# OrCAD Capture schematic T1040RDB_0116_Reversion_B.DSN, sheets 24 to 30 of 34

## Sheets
24 24 POTS3&4: size B
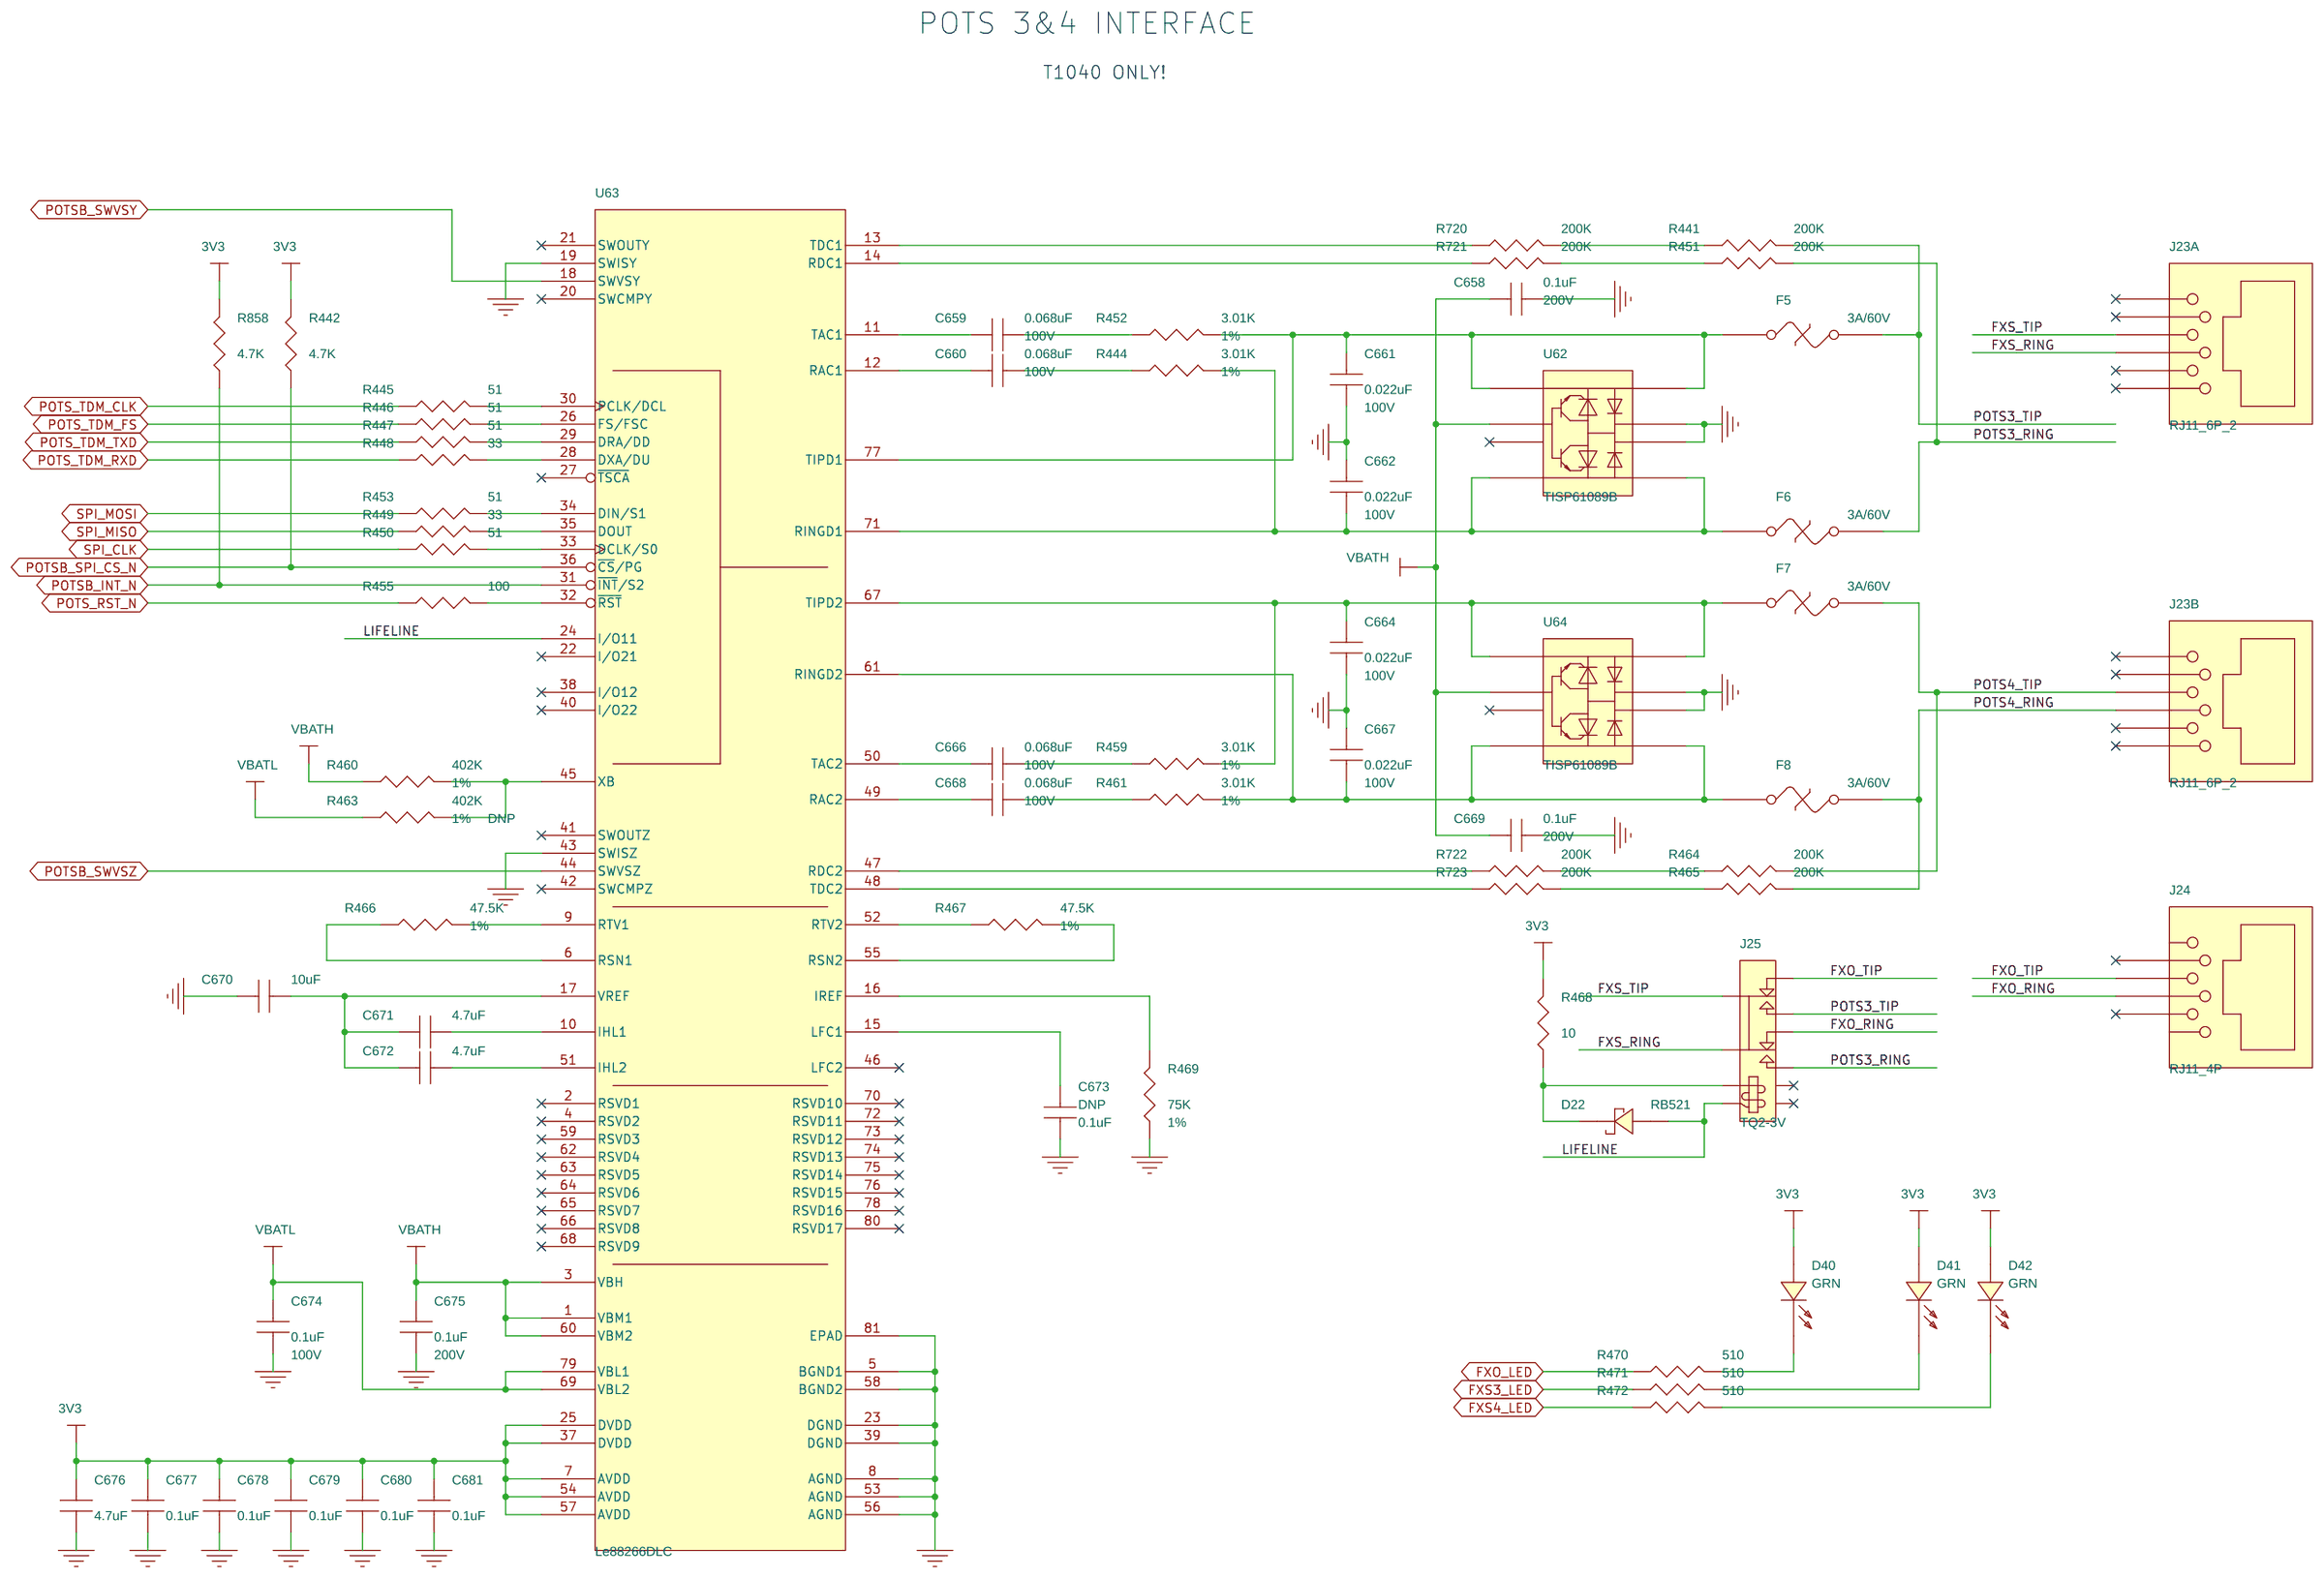
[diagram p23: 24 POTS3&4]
25 25 POTS Pwr: size B
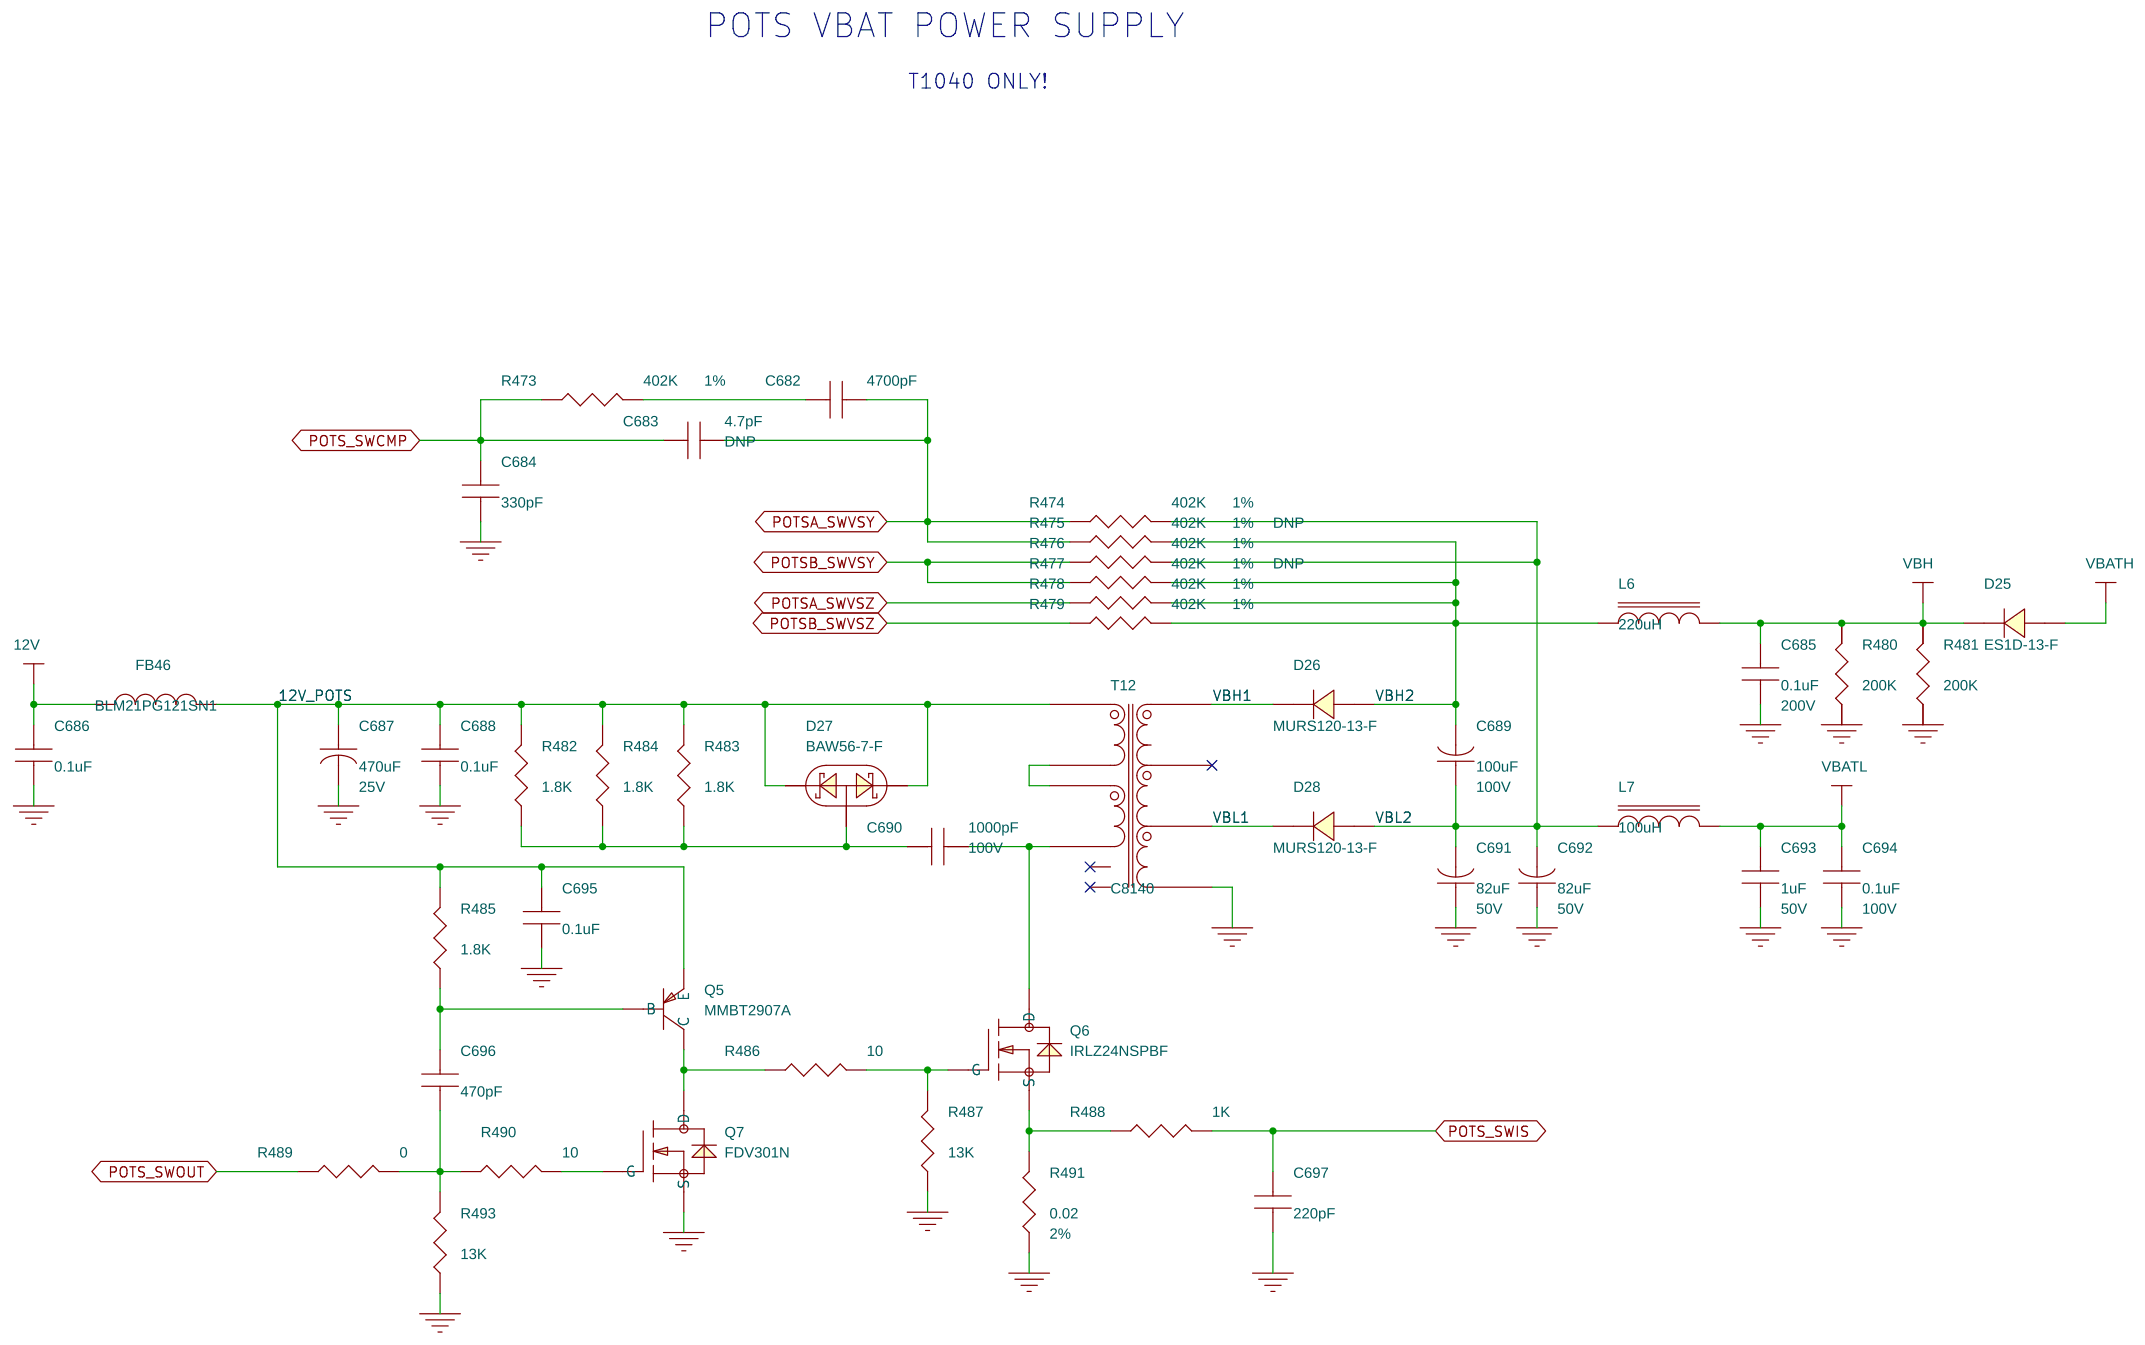
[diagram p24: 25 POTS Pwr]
26 26 CPLD: size B
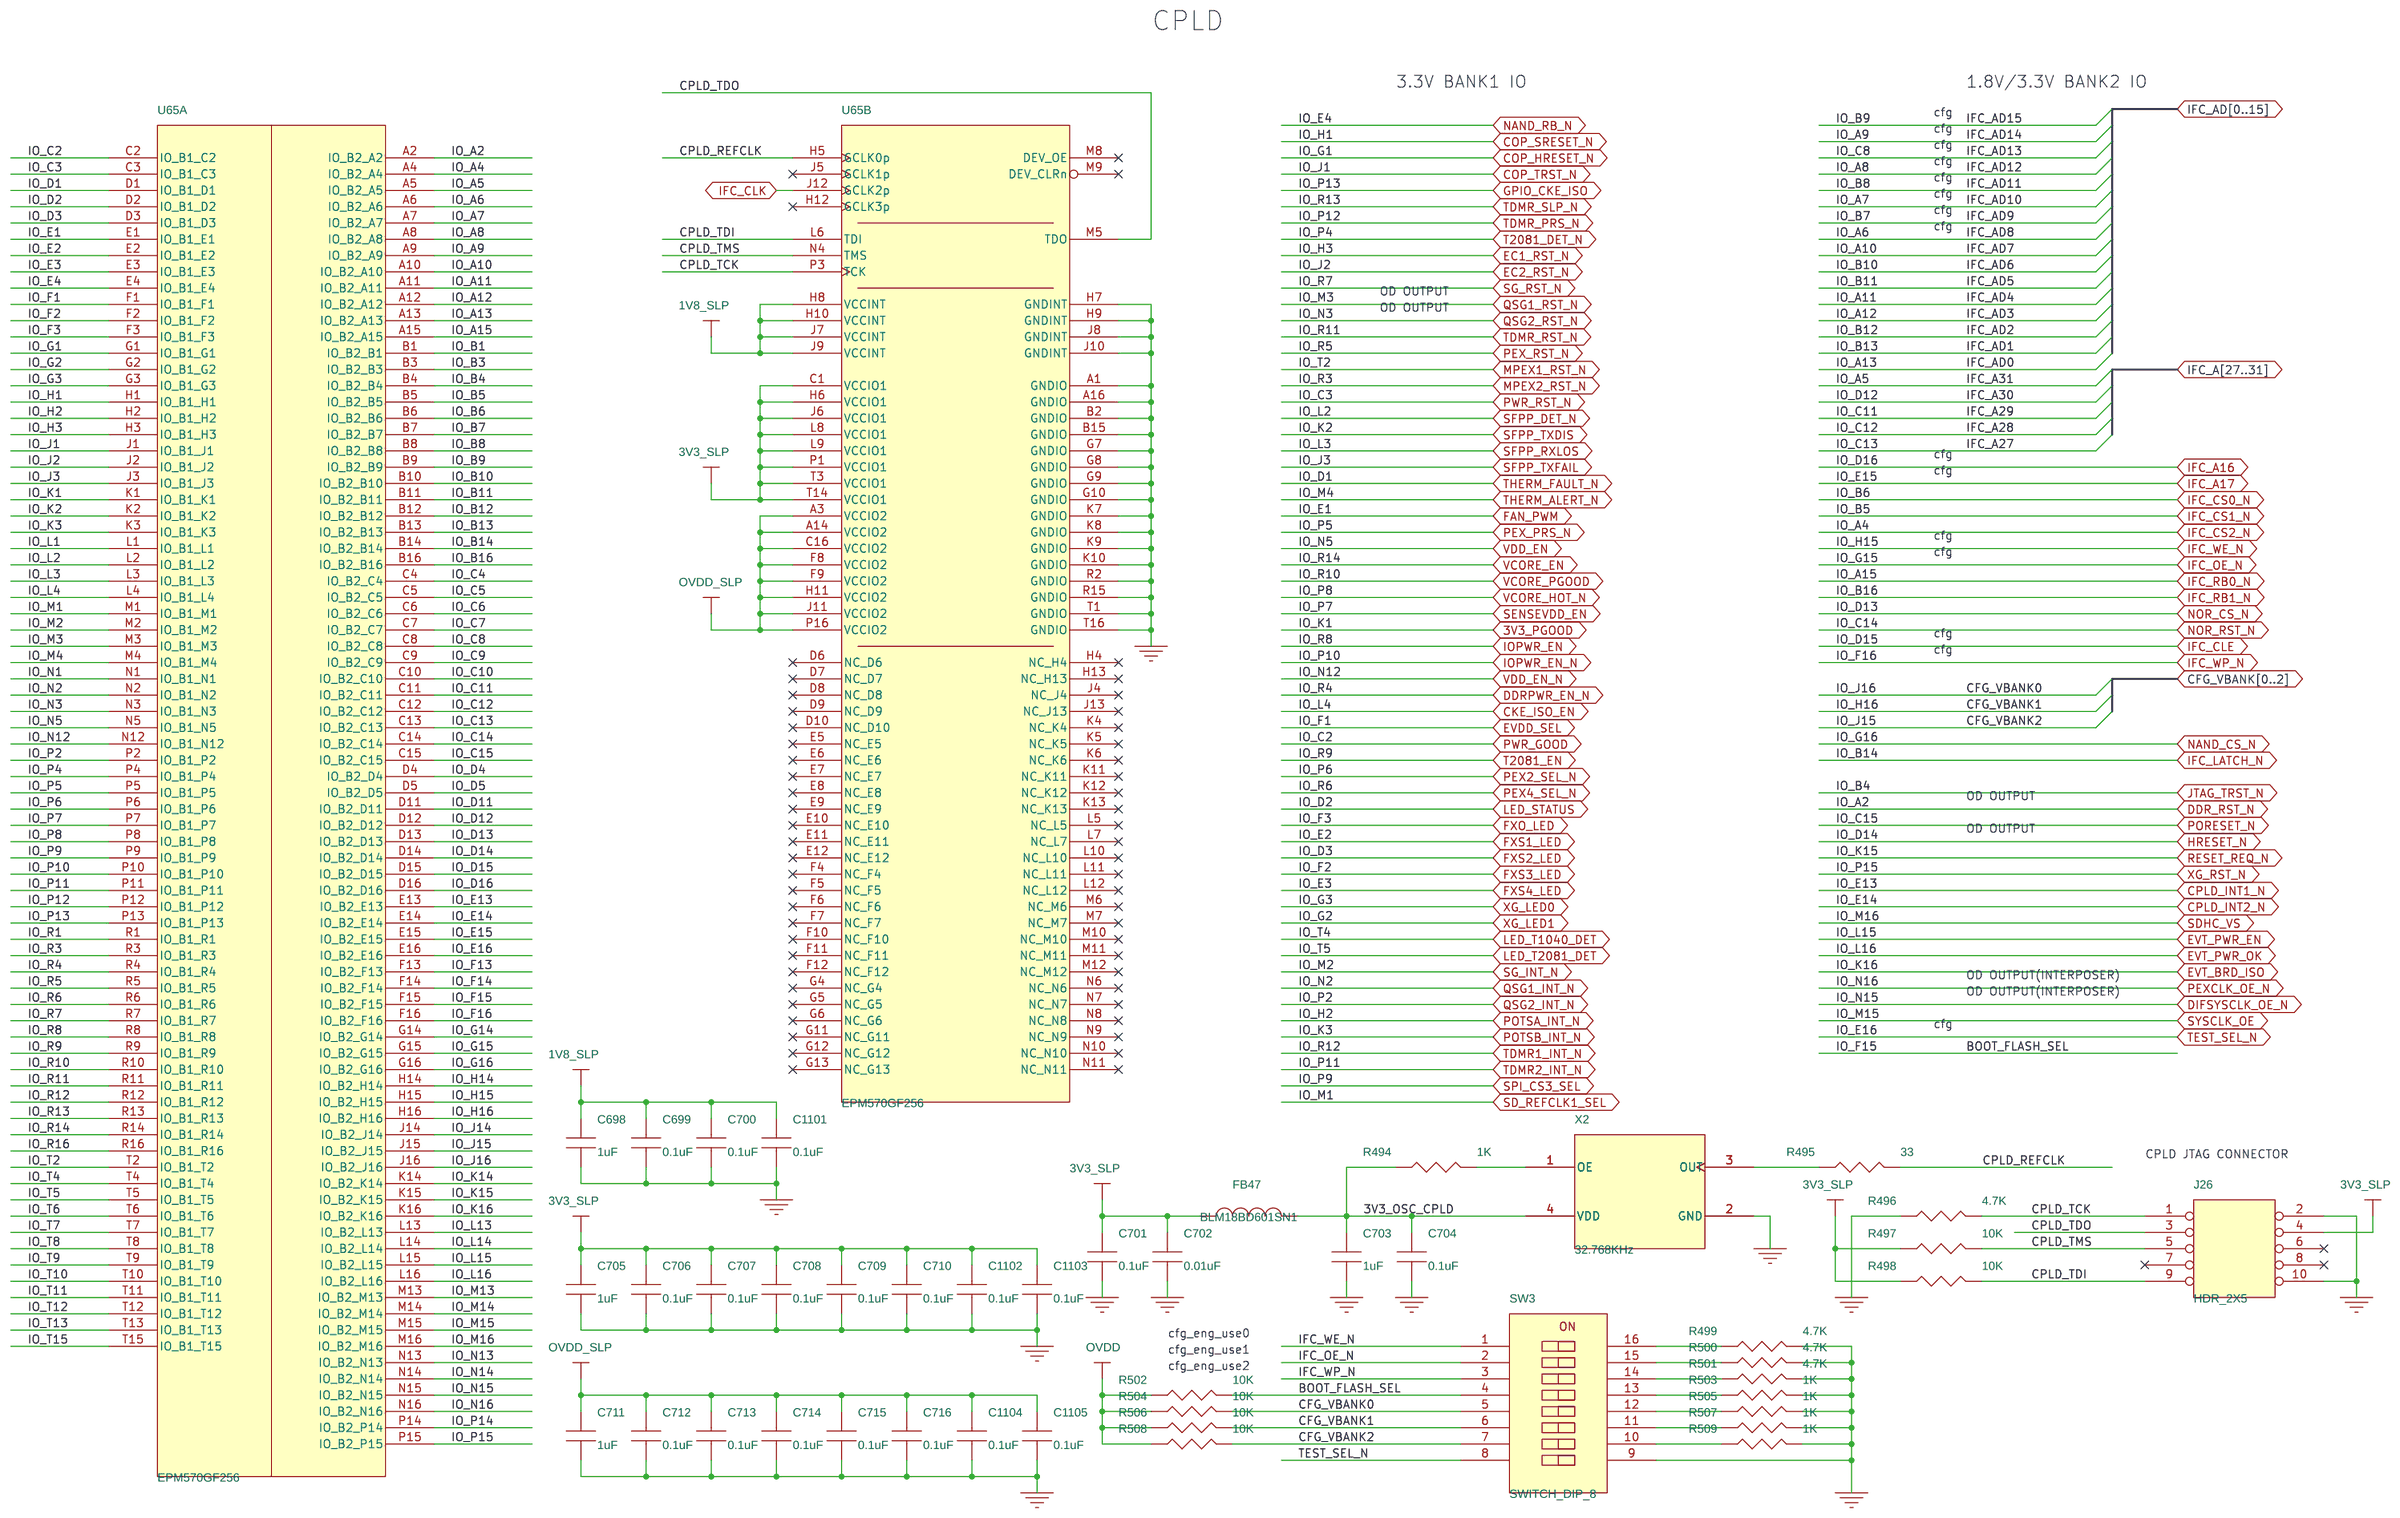
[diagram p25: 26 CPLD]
27 27 Clock 1: size B
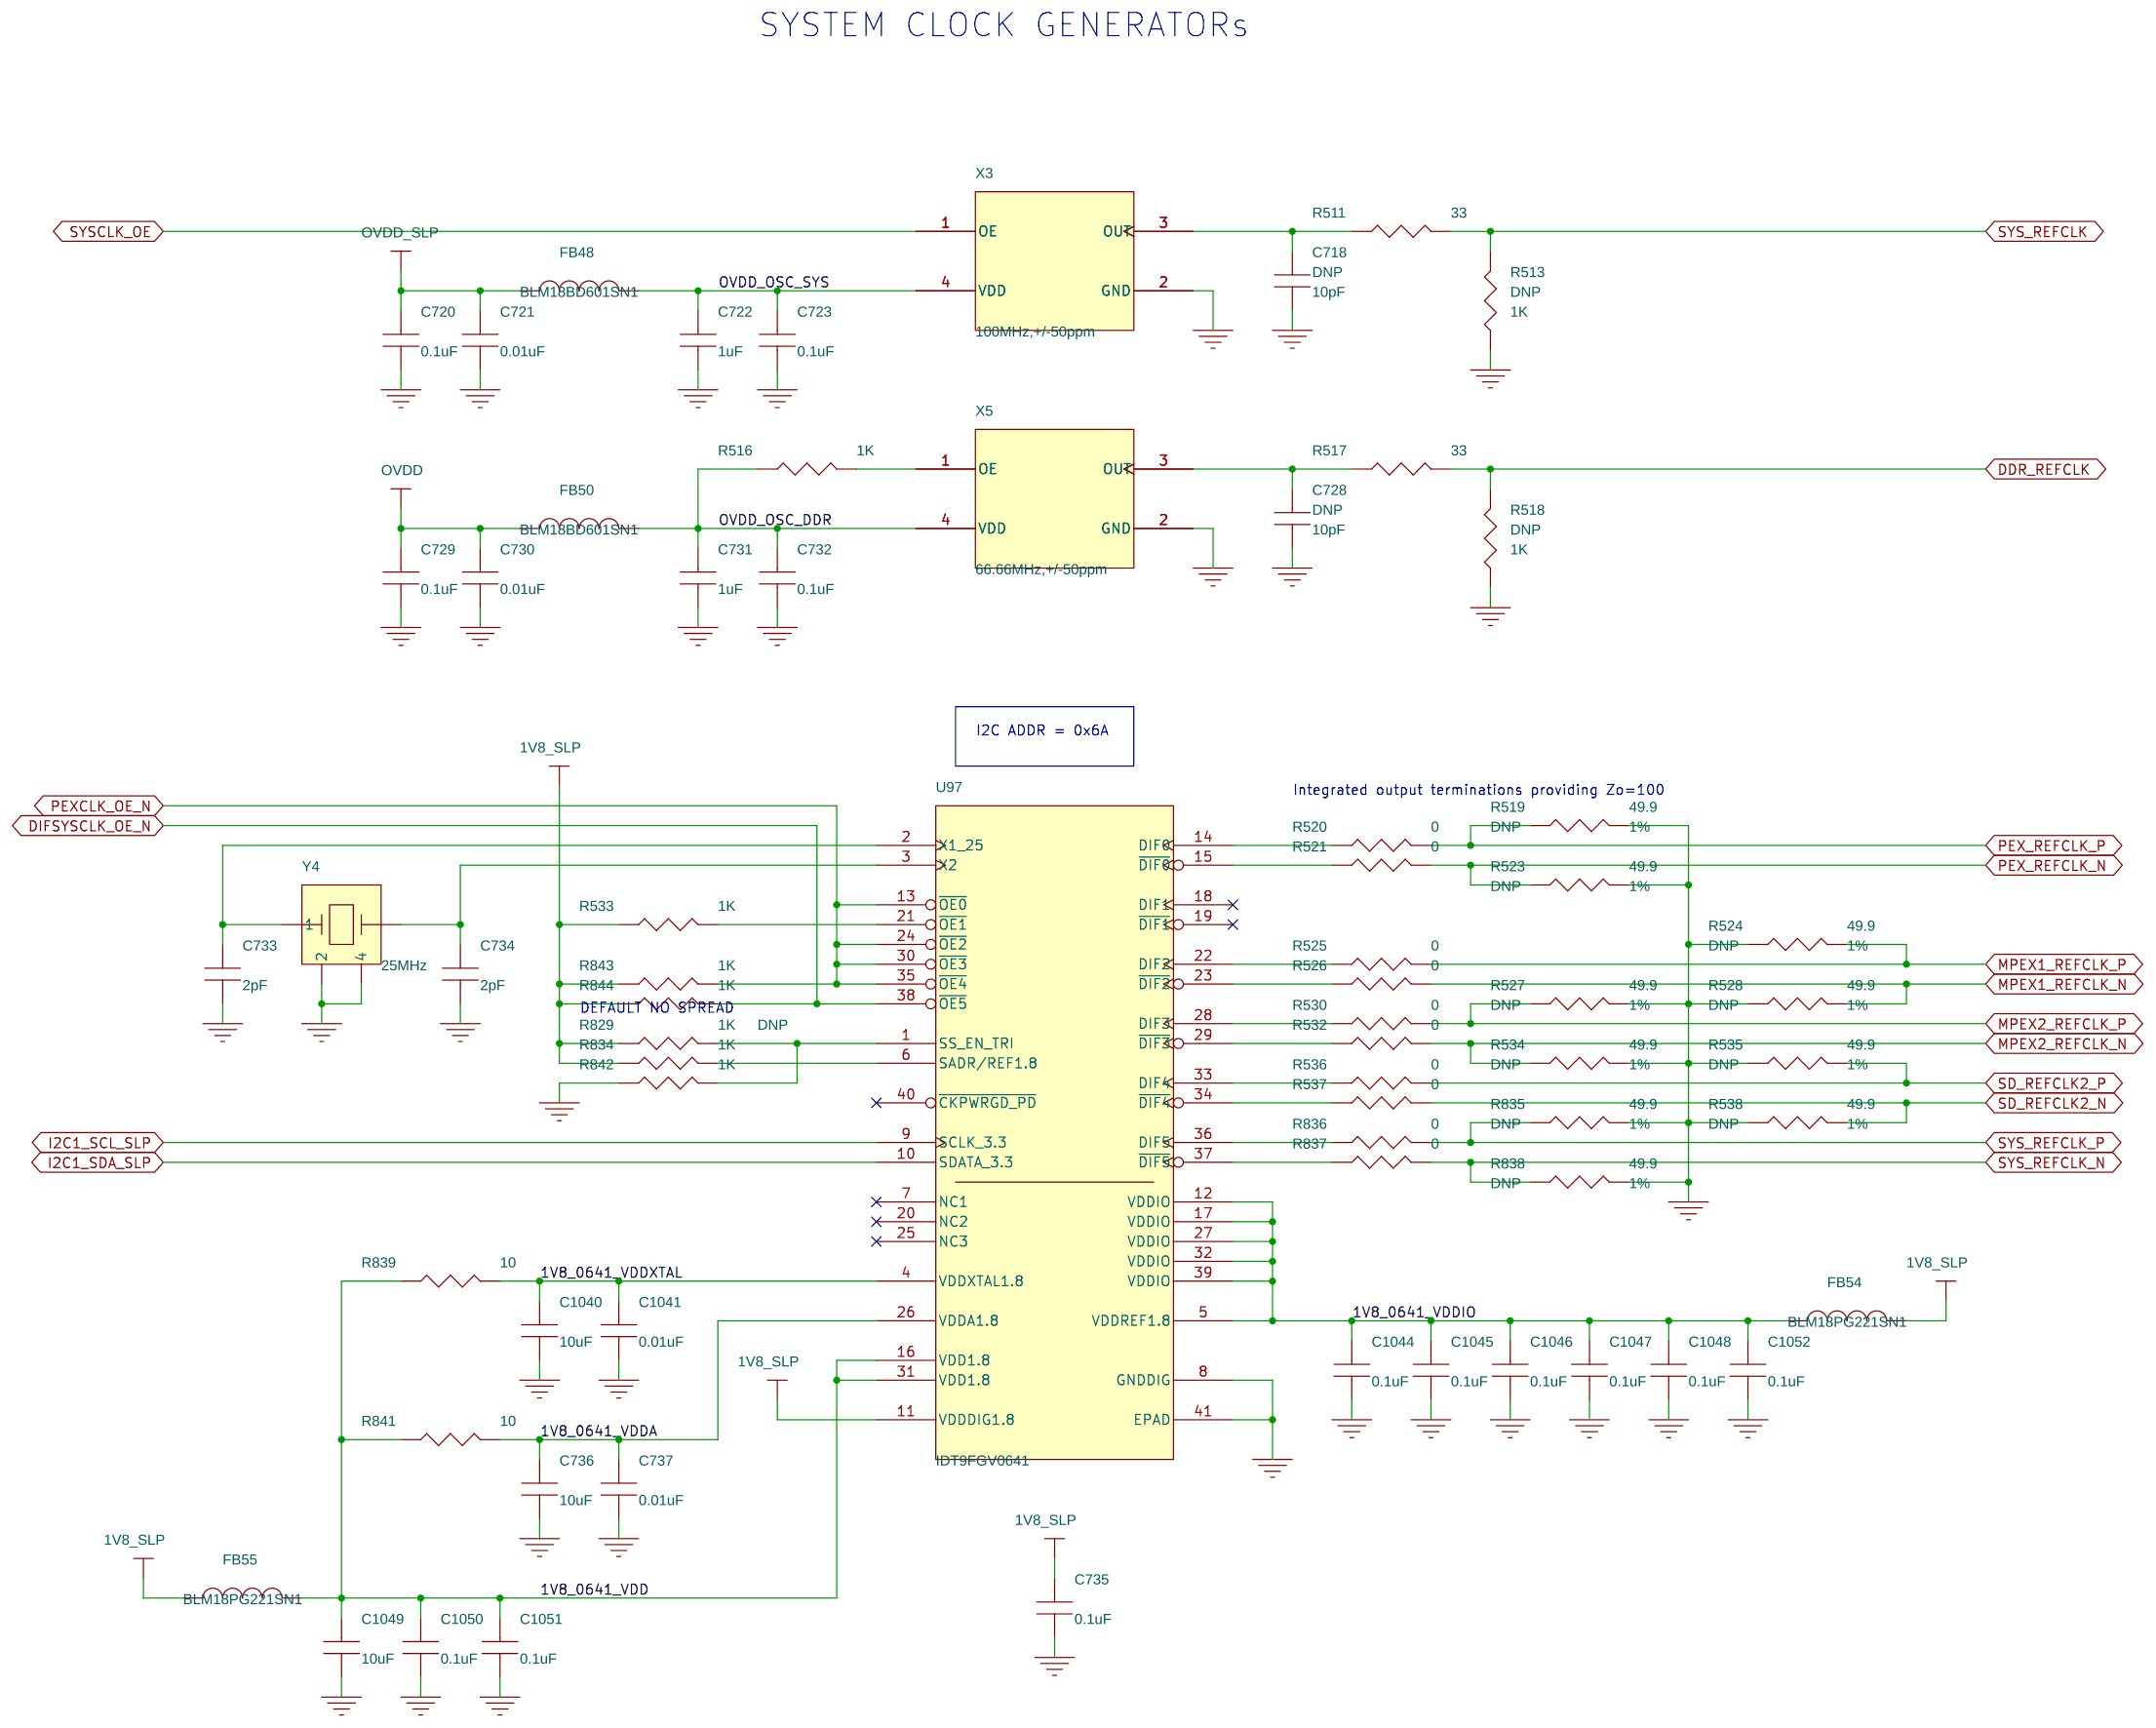
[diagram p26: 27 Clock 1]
28 28 Clock 2: size B
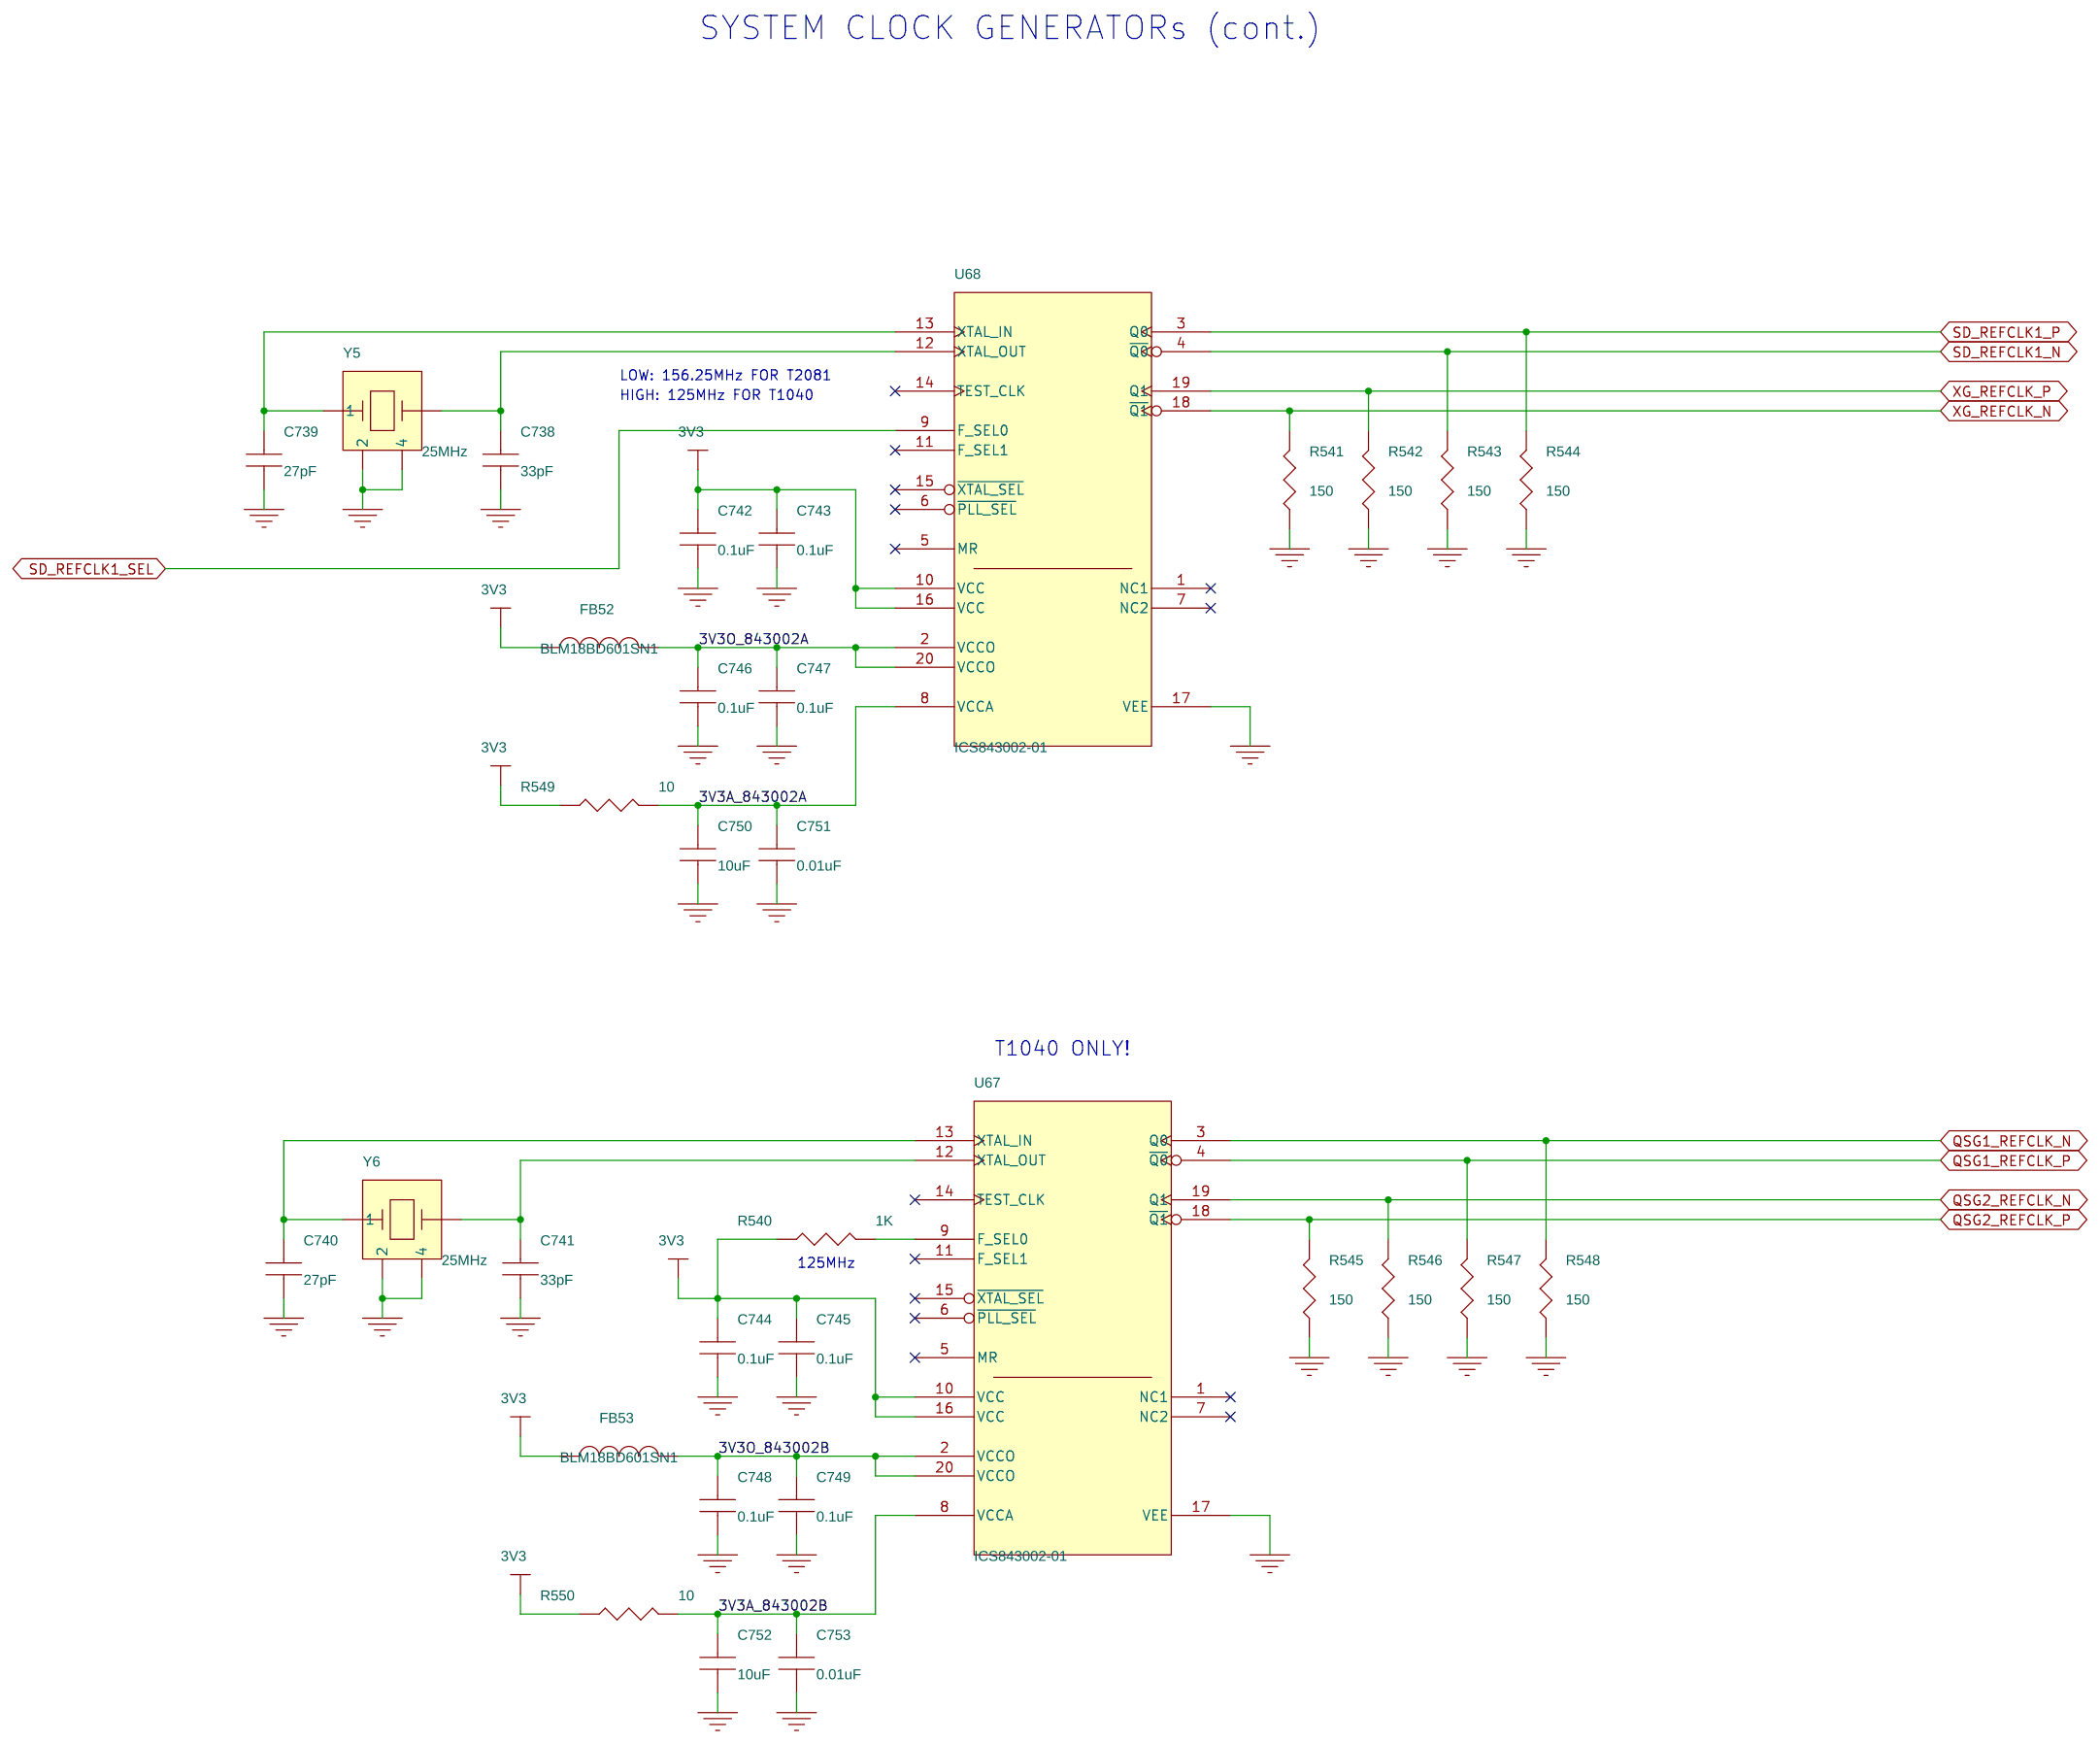
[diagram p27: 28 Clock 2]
29 29 Core Pwr: size B
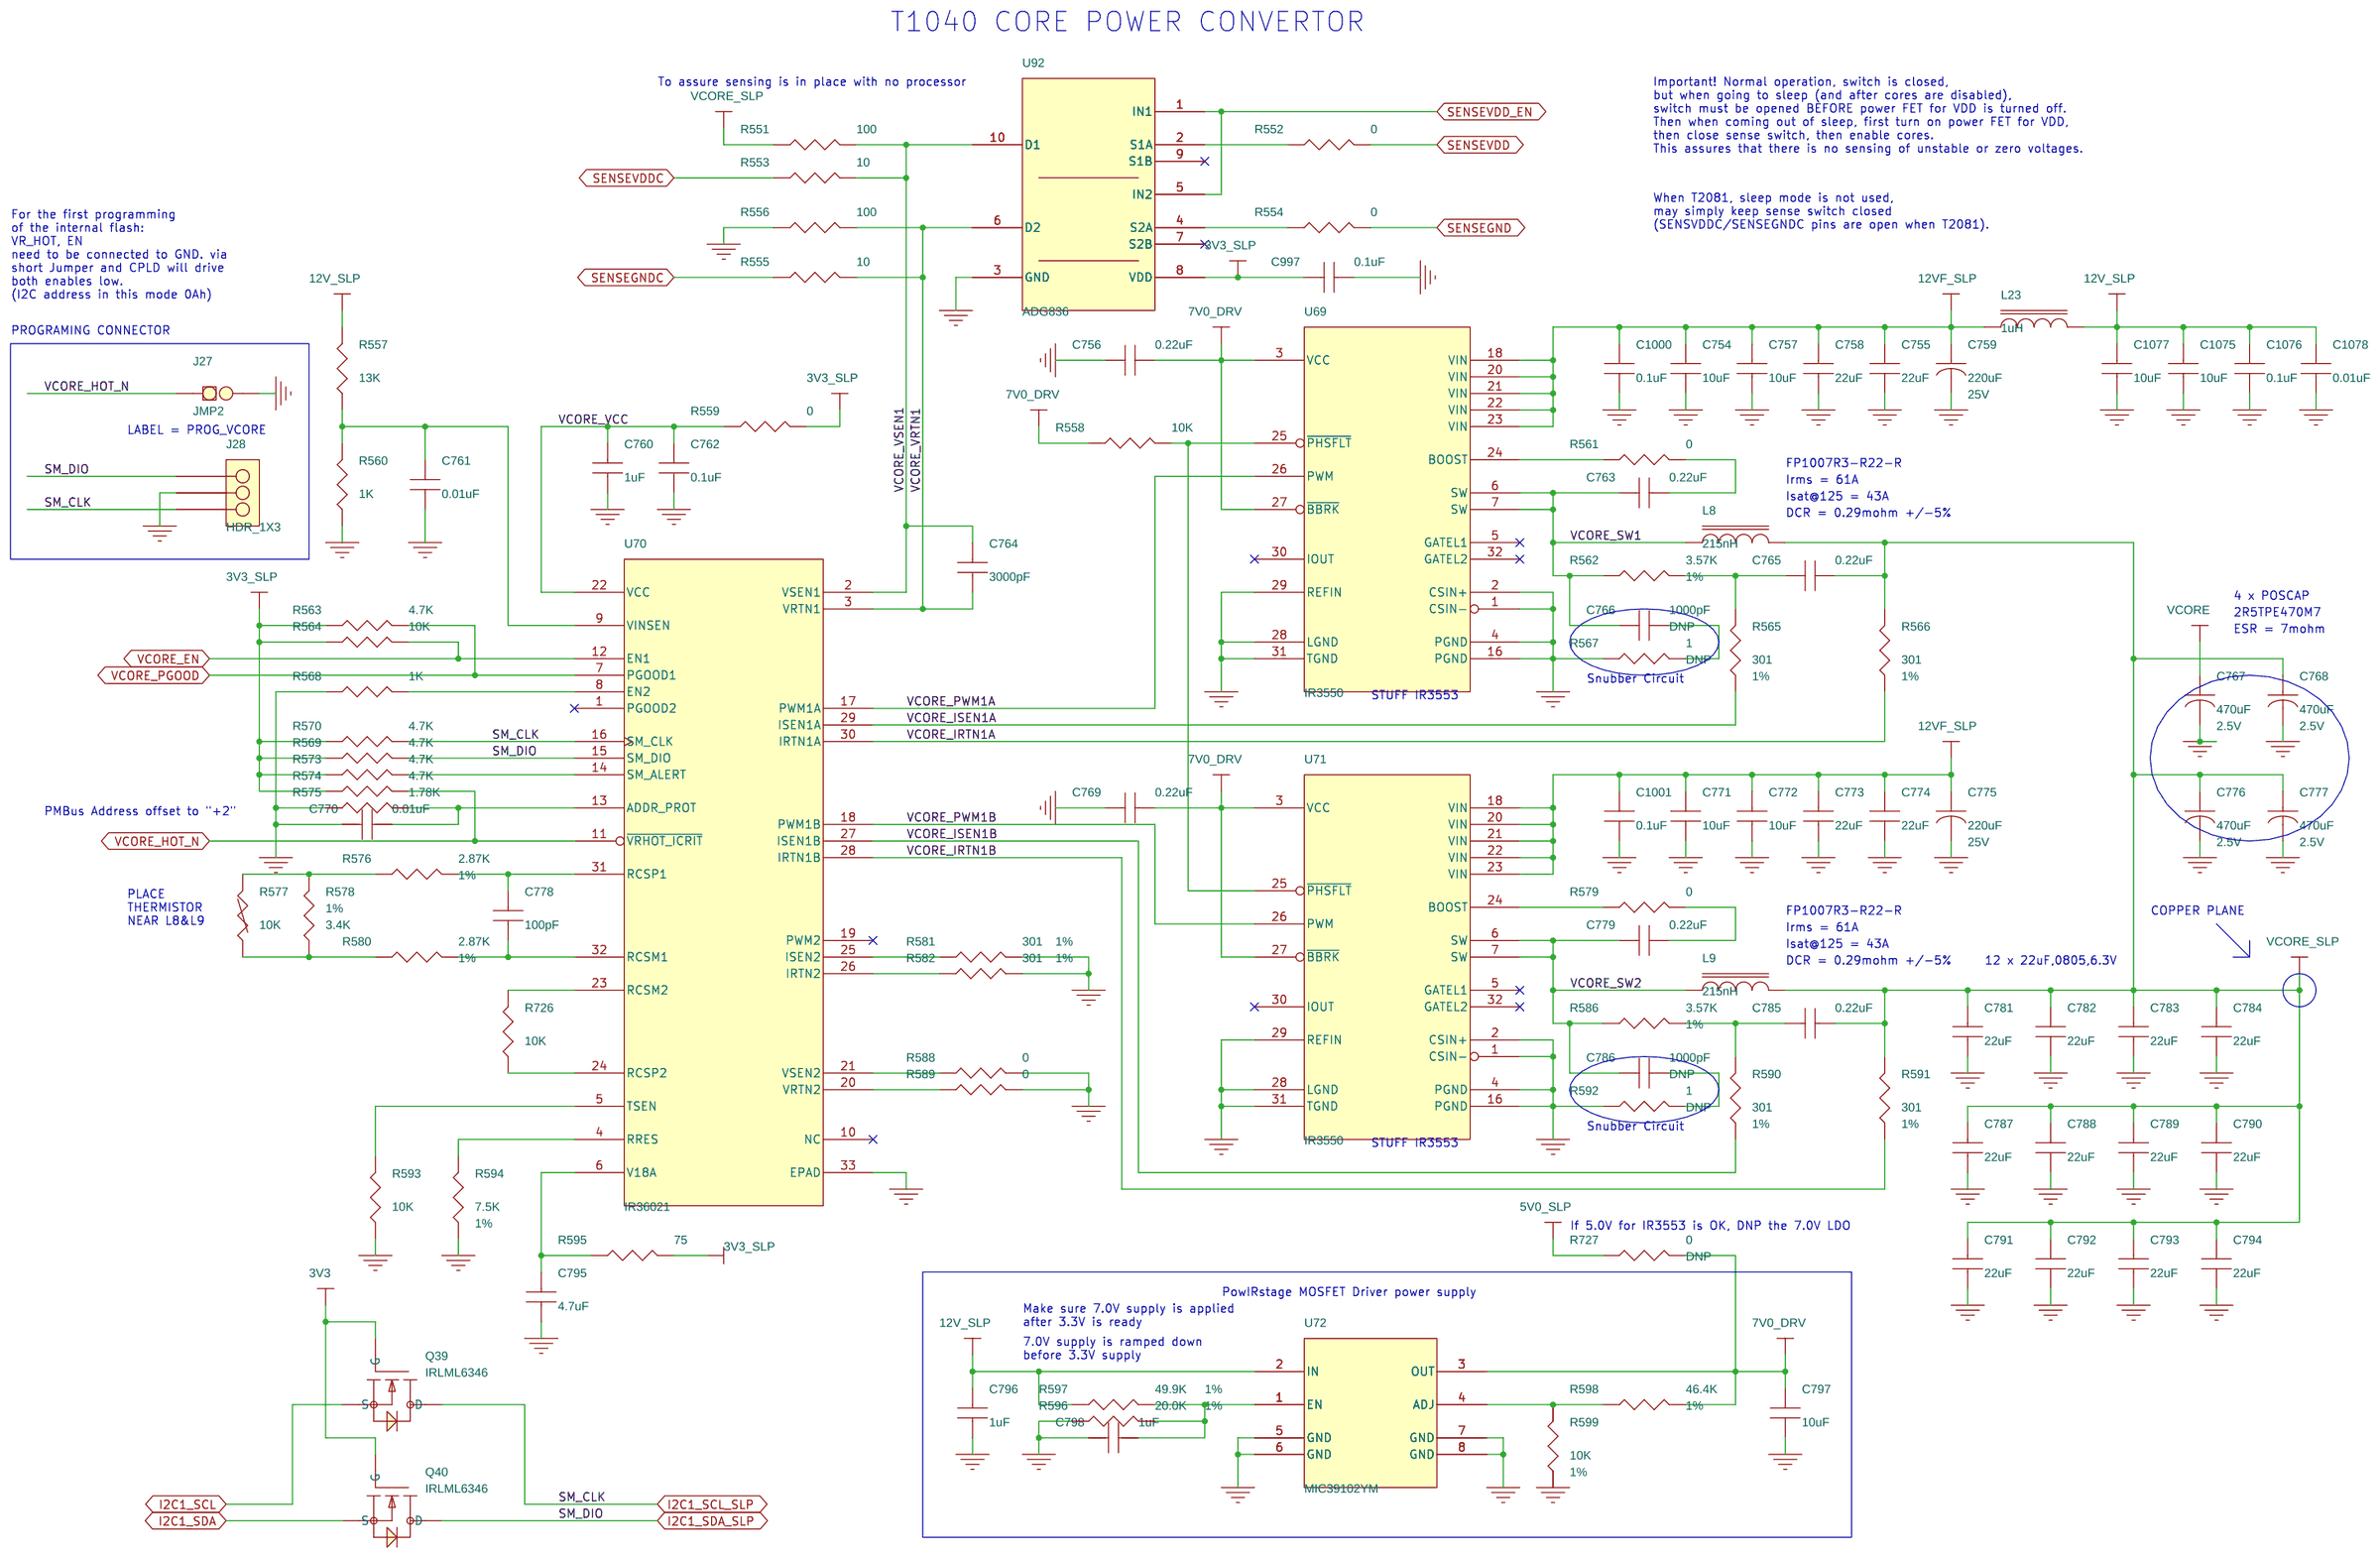
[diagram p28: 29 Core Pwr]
30 30 Other Pwr: size B
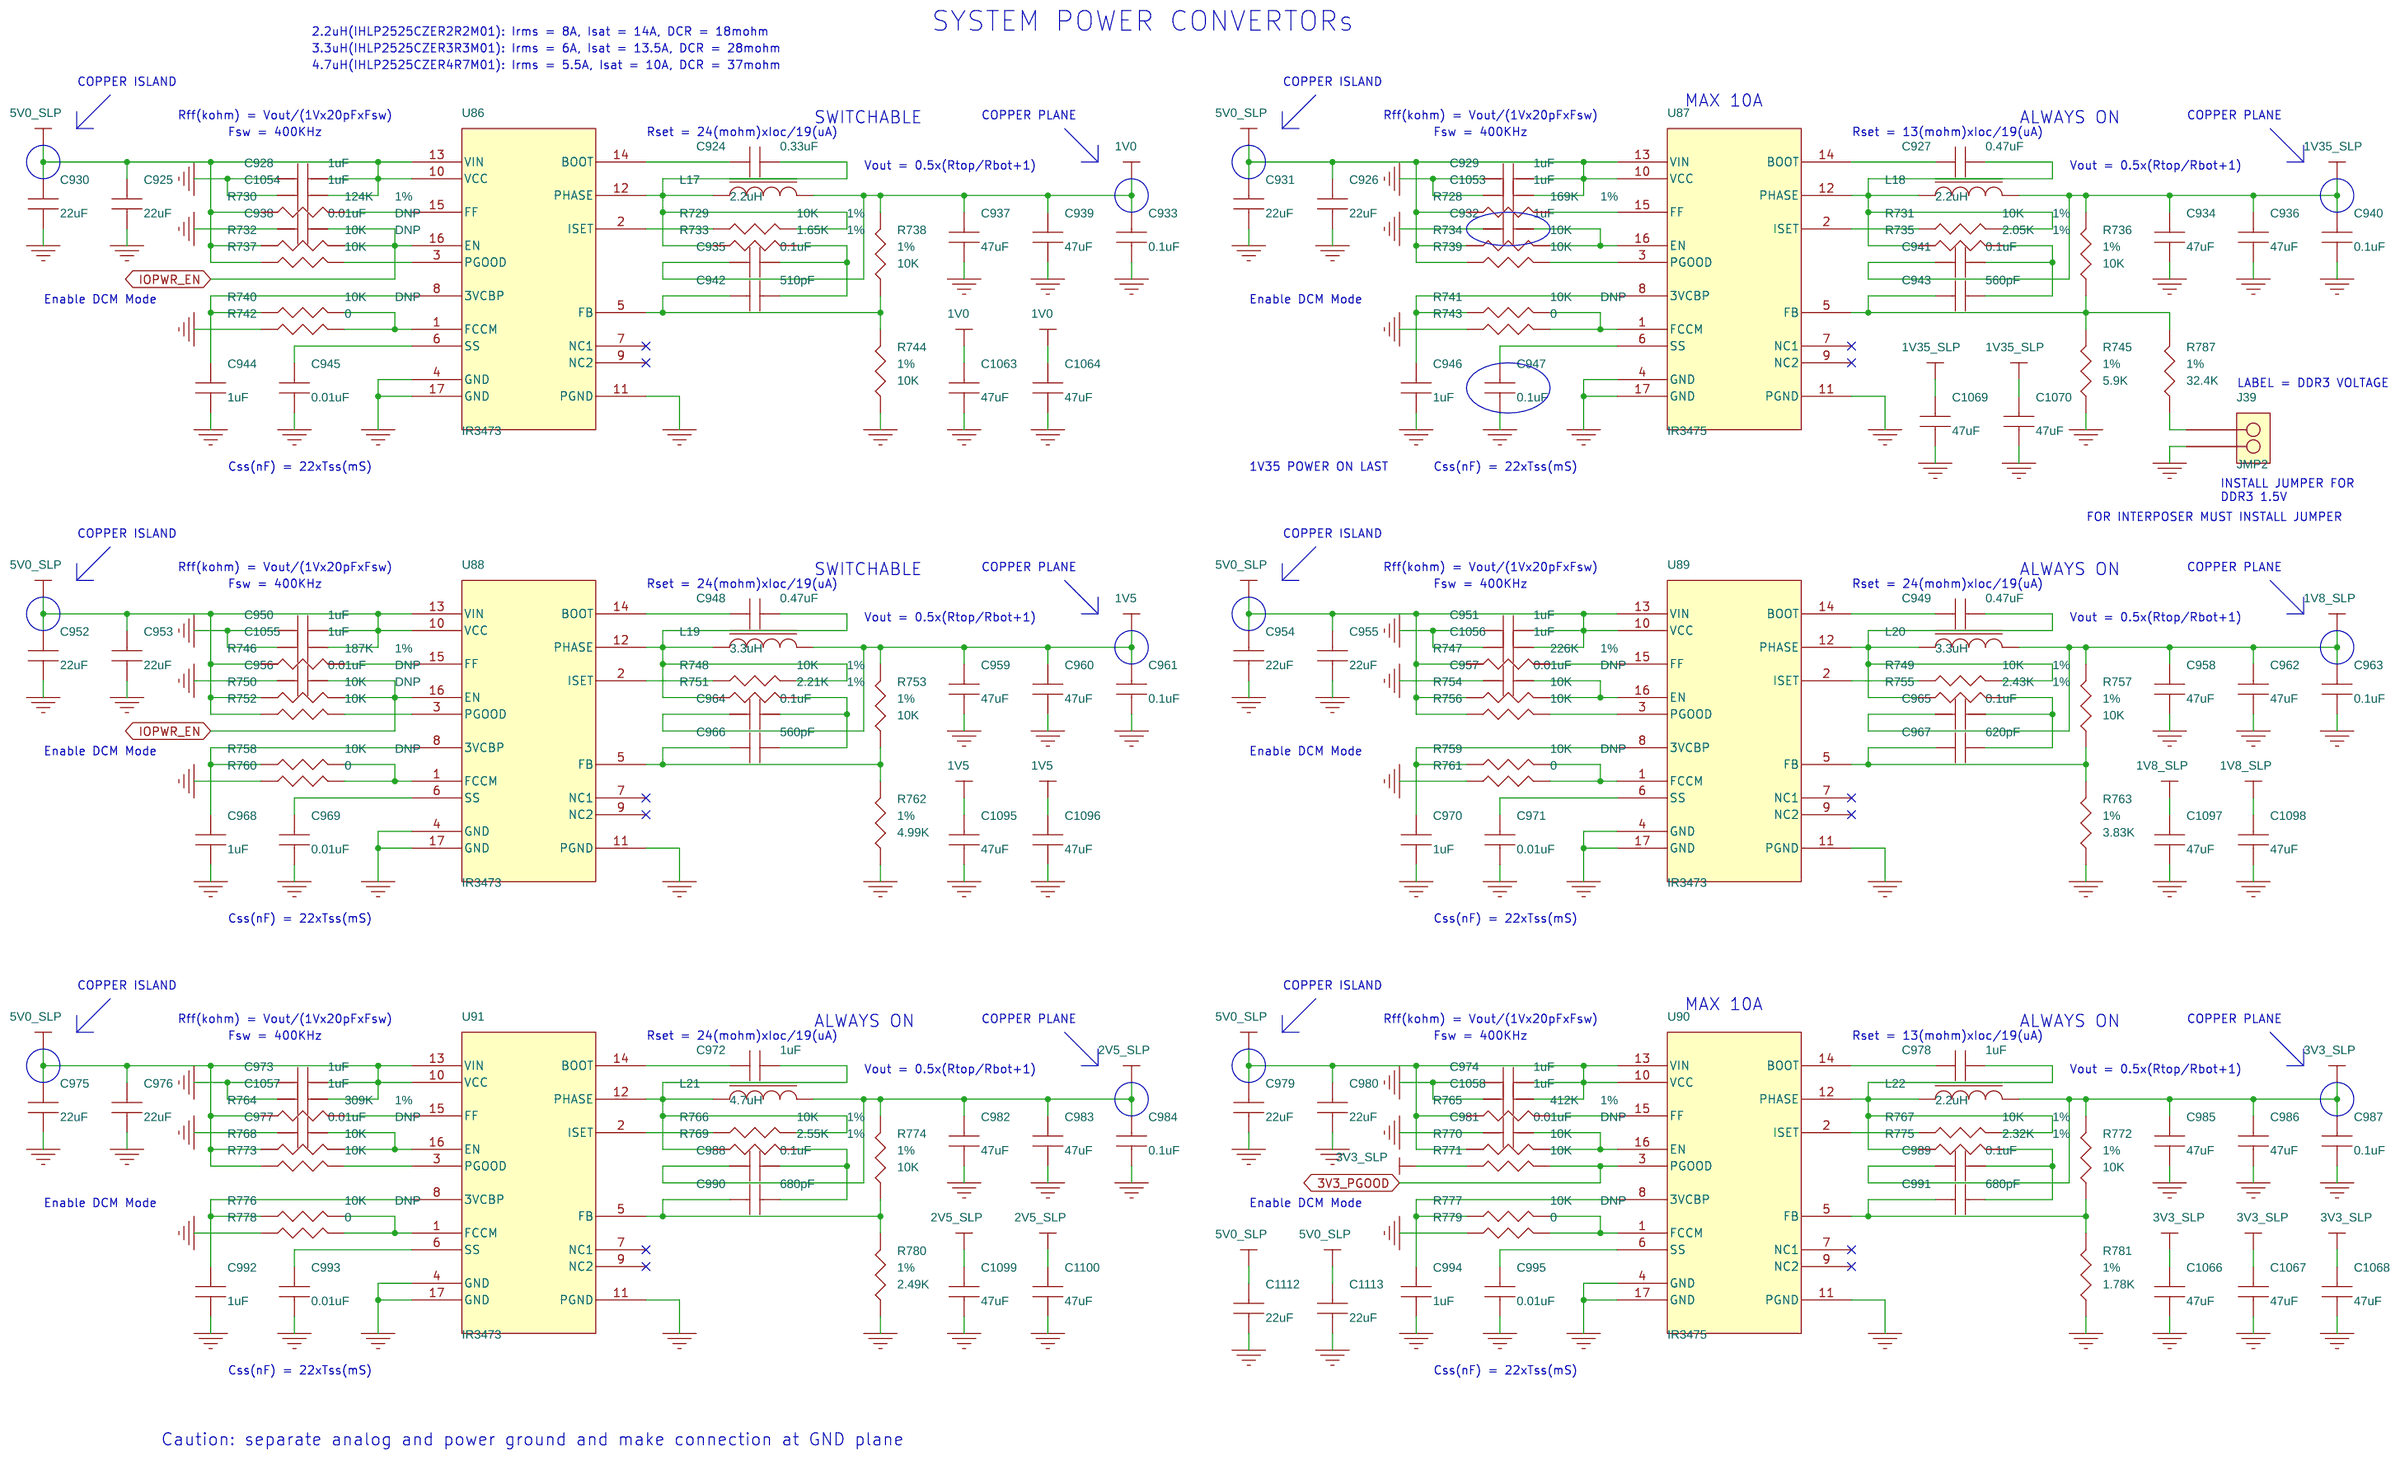
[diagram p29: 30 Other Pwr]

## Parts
sheet 24 POTS3&4
C658  0.1uF  [1206]
C659  0.068uF  [0805]
C660  0.068uF  [0805]
C661  0.022uF  [0805]
C662  0.022uF  [0805]
C664  0.022uF  [0805]
C666  0.068uF  [0805]
C667  0.022uF  [0805]
C668  0.068uF  [0805]
C669  0.1uF  [1206]
C670  10uF  [0603]
C671  4.7uF  [0603]
C672  4.7uF  [0603]
C673  0.1uF  [0402]
C674  0.1uF  [1206]
C675  0.1uF  [1206]
C676  4.7uF  [0603]
C677  0.1uF  [0402]
C678  0.1uF  [0402]
C679  0.1uF  [0402]
C680  0.1uF  [0402]
C681  0.1uF  [0402]
D22  RB521  [sod523]
D40  GRN  [led_pm_1s]
D41  GRN  [led_pm_1s]
D42  GRN  [led_pm_1s]
F5  3A/60V  [ptc_sm013]
F6  3A/60V  [ptc_sm013]
F7  3A/60V  [ptc_sm013]
F8  3A/60V  [ptc_sm013]
J23  RJ11_6P_2  [con_rj11_6p_2x1]  (sections A,B)
J24  RJ11_4P  [con_rj11_4p_1x1]
J25  TQ2-3V  [relay_tq2]
R441  200K  [1206]
R442  4.7K  [0402]
R444  3.01K  [0805]
R445  51  [0402]
R446  51  [0402]
R447  51  [0402]
R448  33  [0402]
R449  33  [0402]
R450  51  [0402]
R451  200K  [1206]
R452  3.01K  [0805]
R453  51  [0402]
R455  100  [0402]
R459  3.01K  [0805]
R460  402K  [0805]
R461  3.01K  [0805]
R463  402K  [0805]
R464  200K  [1206]
R465  200K  [1206]
R466  47.5K  [0402]
R467  47.5K  [0402]
R468  10  [0402]
R469  75K  [0402]
R470  510  [0402]
R471  510  [0402]
R472  510  [0402]
R720  200K  [1206]
R721  200K  [1206]
R722  200K  [1206]
R723  200K  [1206]
R858  4.7K  [0402]
U62  TISP61089B  [so_8]
U63  Le88266DLC  [qfp_p065_80_e780]
U64  TISP61089B  [so_8]
sheet 25 POTS Pwr
C682  4700pF  [0402]
C683  4.7pF  [0402]
C684  330pF  [0402]
C685  0.1uF  [1206]
C686  0.1uF  [0603]
C687  470uF  [cape_p5_b10]
C688  0.1uF  [0603]
C689  100uF  [cape_p5_b12d5]
C690  1000pF  [0603]
C691  82uF  [cape_p3d5_b8]
C692  82uF  [cape_p3d5_b8]
C693  1uF  [1206]
C694  0.1uF  [1206]
C695  0.1uF  [0603]
C696  470pF  [0402]
C697  220pF  [0402]
D25  ES1D-13-F  [sma]
D26  MURS120-13-F  [smb]
D27  BAW56-7-F  [sot23]
D28  MURS120-13-F  [smb]
FB46  BLM21PG121SN1  [0805]
L6  220uH  [ind_swrb07]
L7  100uH  [ind_swrb07]
Q5  MMBT2907A  [sot23]
Q6  IRLZ24NSPBF  [to263]
Q7  FDV301N  [sot23]
R473  402K  [0402]
R474  402K  [0805]
R475  402K  [0805]
R476  402K  [0805]
R477  402K  [0805]
R478  402K  [0805]
R479  402K  [0805]
R480  200K  [0805]
R481  200K  [0805]
R482  1.8K  [0805]
R483  1.8K  [0805]
R484  1.8K  [0805]
R485  1.8K  [0402]
R486  10  [0402]
R487  13K  [0402]
R488  1K  [0402]
R489  0  [0402]
R490  10  [0402]
R491  0.02  [1206]
R493  13K  [0402]
T12  C8140  [xfmr_c8140]
sheet 26 CPLD
C698  1uF  [0402o]
C699  0.1uF  [0402o]
C700  0.1uF  [0402o]
C701  0.1uF  [0402]
C702  0.01uF  [0402]
C703  1uF  [0402]
C704  0.1uF  [0402]
C705  1uF  [0402o]
C706  0.1uF  [0402o]
C707  0.1uF  [0402o]
C708  0.1uF  [0402o]
C709  0.1uF  [0402o]
C710  0.1uF  [0402o]
C711  1uF  [0402o]
C712  0.1uF  [0402o]
C713  0.1uF  [0402o]
C714  0.1uF  [0402o]
C715  0.1uF  [0402o]
C716  0.1uF  [0402o]
C1101  0.1uF  [0402o]
C1102  0.1uF  [0402o]
C1103  0.1uF  [0402o]
C1104  0.1uF  [0402o]
C1105  0.1uF  [0402o]
FB47  BLM18BD601SN1  [0603]
J26  HDR_2X5  [hdr_p254_m_t_2x5]
R494  1K  [0402]
R495  33  [0402]
R496  4.7K  [0402]
R497  10K  [0402]
R498  10K  [0402]
R499  4.7K  [0402]
R500  4.7K  [0402]
R501  4.7K  [0402]
R502  10K  [0402]
R503  1K  [0402]
R504  10K  [0402]
R505  1K  [0402]
R506  10K  [0402]
R507  1K  [0402]
R508  10K  [0402]
R509  1K  [0402]
SW3  SWITCH_DIP_8  [con_switch_x8]
U65  EPM570GF256  [bga_p100_256]  (sections A,B)
X2  32.768KHz  [osc_32x25_4]
sheet 27 Clock 1
C718  10pF  [0402]
C720  0.1uF  [0402]
C721  0.01uF  [0402]
C722  1uF  [0402]
C723  0.1uF  [0402]
C728  10pF  [0402]
C729  0.1uF  [0402]
C730  0.01uF  [0402]
C731  1uF  [0402]
C732  0.1uF  [0402]
C733  2pF  [0402]
C734  2pF  [0402]
C735  0.1uF  [0402]
C736  10uF  [0603]
C737  0.01uF  [0402]
C1040  10uF  [0603]
C1041  0.01uF  [0402]
C1044  0.1uF  [0402]
C1045  0.1uF  [0402]
C1046  0.1uF  [0402]
C1047  0.1uF  [0402]
C1048  0.1uF  [0402]
C1049  10uF  [0603]
C1050  0.1uF  [0402]
C1051  0.1uF  [0402]
C1052  0.1uF  [0402]
FB48  BLM18BD601SN1  [0603]
FB50  BLM18BD601SN1  [0603]
FB54  BLM18PG221SN1  [0603]
FB55  BLM18PG221SN1  [0603]
R511  33  [0402]
R513  1K  [0402]
R516  1K  [0402]
R517  33  [0402]
R518  1K  [0402]
R519  49.9  [0402]
R520  0  [0402]
R521  0  [0402]
R523  49.9  [0402]
R524  49.9  [0402]
R525  0  [0402]
R526  0  [0402]
R527  49.9  [0402]
R528  49.9  [0402]
R530  0  [0402]
R532  0  [0402]
R533  1K  [0402]
R534  49.9  [0402]
R535  49.9  [0402]
R536  0  [0402]
R537  0  [0402]
R538  49.9  [0402]
R829  1K  [0402]
R834  1K  [0402]
R835  49.9  [0402]
R836  0  [0402]
R837  0  [0402]
R838  49.9  [0402]
R839  10  [0402]
R841  10  [0402]
R842  1K  [0402]
R843  1K  [0402]
R844  1K  [0402]
U97  IDT9FGV0641  [qfn_p040_d040_b500_40_e370]
X3  100MHz,+/-50ppm  [osc_7x5_4]
X5  66.66MHz,+/-50ppm  [osc_7x5_4]
Y4  25MHz  [cry_32x25_4]
sheet 28 Clock 2
C738  33pF  [0402]
C739  27pF  [0402]
C740  27pF  [0402]
C741  33pF  [0402]
C742  0.1uF  [0402]
C743  0.1uF  [0402]
C744  0.1uF  [0402]
C745  0.1uF  [0402]
C746  0.1uF  [0402]
C747  0.1uF  [0402]
C748  0.1uF  [0402]
C749  0.1uF  [0402]
C750  10uF  [0603]
C751  0.01uF  [0402]
C752  10uF  [0603]
C753  0.01uF  [0402]
FB52  BLM18BD601SN1  [0603]
FB53  BLM18BD601SN1  [0603]
R540  1K  [0402]
R541  150  [0402]
R542  150  [0402]
R543  150  [0402]
R544  150  [0402]
R545  150  [0402]
R546  150  [0402]
R547  150  [0402]
R548  150  [0402]
R549  10  [0402]
R550  10  [0402]
U67  ICS843002-01  [tssop_20]
U68  ICS843002-01  [tssop_20]
Y5  25MHz  [cry_32x25_4]
Y6  25MHz  [cry_32x25_4]
sheet 29 Core Pwr
C754  10uF  [1206]
C755  22uF  [1210]
C756  0.22uF  [0402]
C757  10uF  [1206]
C758  22uF  [1210]
C759  220uF  [cape_b8]
C760  1uF  [0402]
C761  0.01uF  [0402]
C762  0.1uF  [0402]
C763  0.22uF  [0402]
C764  3000pF  [0402]
C765  0.22uF  [0402]
C766  1000pF  [0603]
C767  470uF  [7343]
C768  470uF  [7343]
C769  0.22uF  [0402]
C770  0.01uF  [0402]
C771  10uF  [1206]
C772  10uF  [1206]
C773  22uF  [1210]
C774  22uF  [1210]
C775  220uF  [cape_b8]
C776  470uF  [7343]
C777  470uF  [7343]
C778  100pF  [0402]
C779  0.22uF  [0402]
C781  22uF  [0805]
C782  22uF  [0805]
C783  22uF  [0805]
C784  22uF  [0805]
C785  0.22uF  [0402]
C786  1000pF  [0603]
C787  22uF  [0805]
C788  22uF  [0805]
C789  22uF  [0805]
C790  22uF  [0805]
C791  22uF  [0805]
C792  22uF  [0805]
C793  22uF  [0805]
C794  22uF  [0805]
C795  4.7uF  [0603]
C796  1uF  [0603]
C797  10uF  [0805]
C798  1uF  [0603]
C997  0.1uF  [0402]
C1000  0.1uF  [0603]
C1001  0.1uF  [0603]
C1075  10uF  [1206]
C1076  0.1uF  [0603]
C1077  10uF  [1206]
C1078  0.01uF  [0402]
J27  JMP2  [jmp_p254_t_1x2]
J28  HDR_1X3  [hdr_p254_m_t_1x3]
L8  215nH  [ind_fp1007]
L9  215nH  [ind_fp1007]
L23  1uH  [ind_ihlp_2525]
Q39  IRLML6346  [sot23]
Q40  IRLML6346  [sot23]
R551  100  [0402]
R552  0  [0402]
R553  10  [0402]
R554  0  [0402]
R555  10  [0402]
R556  100  [0402]
R557  13K  [0402]
R558  10K  [0402]
R559  0  [0402]
R560  1K  [0402]
R561  0  [0402]
R562  3.57K  [0402]
R563  4.7K  [0402]
R564  10K  [0402]
R565  301  [0402]
R566  301  [0402]
R567  1  [1206]
R568  1K  [0402]
R569  4.7K  [0402]
R570  4.7K  [0402]
R573  4.7K  [0402]
R574  4.7K  [0402]
R575  1.78K  [0402]
R576  2.87K  [0402]
R577  10K  [0603]
R578  3.4K  [0402]
R579  0  [0402]
R580  2.87K  [0402]
R581  301  [0402]
R582  301  [0402]
R586  3.57K  [0402]
R588  0  [0402]
R589  0  [0402]
R590  301  [0402]
R591  301  [0402]
R592  1  [1206]
R593  10K  [0402]
R594  7.5K  [0402]
R595  75  [0402]
R596  20.0K  [0402]
R597  49.9K  [0402]
R598  46.4K  [0402]
R599  10K  [0402]
R726  10K  [0402]
R727  0  [0402]
U69  IR3550  [qfn_ir3550]
U70  IR36021  [qfn_p050_d040_b500_32_e345]
U71  IR3550  [qfn_ir3550]
U72  MIC39102YM  [so_8]
U92  ADG836  [msop_10]
sheet 30 Other Pwr
C924  0.33uF  [0603]
C925  22uF  [1206]
C926  22uF  [1206]
C927  0.47uF  [0603]
C928  1uF  [0603]
C929  1uF  [0603]
C930  22uF  [1206]
C931  22uF  [1206]
C932  1uF  [0402]
C933  0.1uF  [0402]
C934  47uF  [0805]
C935  0.1uF  [0402]
C936  47uF  [0805]
C937  47uF  [0805]
C938  0.01uF  [0402]
C939  47uF  [0805]
C940  0.1uF  [0402]
C941  0.1uF  [0402]
C942  510pF  [0402]
C943  560pF  [0402]
C944  1uF  [0402]
C945  0.01uF  [0402]
C946  1uF  [0402]
C947  0.1uF  [0402]
C948  0.47uF  [0603]
C949  0.47uF  [0603]
C950  1uF  [0603]
C951  1uF  [0603]
C952  22uF  [1206]
C953  22uF  [1206]
C954  22uF  [1206]
C955  22uF  [1206]
C956  0.01uF  [0402]
C957  0.01uF  [0402]
C958  47uF  [0805]
C959  47uF  [0805]
C960  47uF  [0805]
C961  0.1uF  [0402]
C962  47uF  [0805]
C963  0.1uF  [0402]
C964  0.1uF  [0402]
C965  0.1uF  [0402]
C966  560pF  [0402]
C967  620pF  [0402]
C968  1uF  [0402]
C969  0.01uF  [0402]
C970  1uF  [0402]
C971  0.01uF  [0402]
C972  1uF  [0603]
C973  1uF  [0603]
C974  1uF  [0603]
C975  22uF  [1206]
C976  22uF  [1206]
C977  0.01uF  [0402]
C978  1uF  [0603]
C979  22uF  [1206]
C980  22uF  [1206]
C981  0.01uF  [0402]
C982  47uF  [0805]
C983  47uF  [0805]
C984  0.1uF  [0402]
C985  47uF  [0805]
C986  47uF  [0805]
C987  0.1uF  [0402]
C988  0.1uF  [0402]
C989  0.1uF  [0402]
C990  680pF  [0402]
C991  680pF  [0402]
C992  1uF  [0402]
C993  0.01uF  [0402]
C994  1uF  [0402]
C995  0.01uF  [0402]
C1053  1uF  [0603]
C1054  1uF  [0603]
C1055  1uF  [0603]
C1056  1uF  [0603]
C1057  1uF  [0603]
C1058  1uF  [0603]
C1063  47uF  [0805]
C1064  47uF  [0805]
C1066  47uF  [0805]
C1067  47uF  [0805]
C1068  47uF  [0805]
C1069  47uF  [0805]
C1070  47uF  [0805]
C1095  47uF  [0805]
C1096  47uF  [0805]
C1097  47uF  [0805]
C1098  47uF  [0805]
C1099  47uF  [0805]
C1100  47uF  [0805]
C1112  22uF  [1206]
C1113  22uF  [1206]
J39  JMP2  [jmp_p254_t_1x2]
L17  2.2uH  [ind_ihlp_2525]
L18  2.2uH  [ind_ihlp_2525]
L19  3.3uH  [ind_ihlp_2525]
L20  3.3uH  [ind_ihlp_2525]
L21  4.7uH  [ind_ihlp_2525]
L22  2.2uH  [ind_ihlp_2525]
R728  169K  [0402]
R729  10K  [0402]
R730  124K  [0402]
R731  10K  [0402]
R732  10K  [0402]
R733  1.65K  [0402]
R734  10K  [0402]
R735  2.05K  [0402]
R736  10K  [0402]
R737  10K  [0402]
R738  10K  [0402]
R739  10K  [0402]
R740  10K  [0402]
R741  10K  [0402]
R742  0  [0402]
R743  0  [0402]
R744  10K  [0402]
R745  5.9K  [0402]
R746  187K  [0402]
R747  226K  [0402]
R748  10K  [0402]
R749  10K  [0402]
R750  10K  [0402]
R751  2.21K  [0402]
R752  10K  [0402]
R753  10K  [0402]
R754  10K  [0402]
R755  2.43K  [0402]
R756  10K  [0402]
R757  10K  [0402]
R758  10K  [0402]
R759  10K  [0402]
R760  0  [0402]
R761  0  [0402]
R762  4.99K  [0402]
R763  3.83K  [0402]
R764  309K  [0402]
R765  412K  [0402]
R766  10K  [0402]
R767  10K  [0402]
R768  10K  [0402]
R769  2.55K  [0402]
R770  10K  [0402]
R771  10K  [0402]
R772  10K  [0402]
R773  10K  [0402]
R774  10K  [0402]
R775  2.32K  [0402]
R776  10K  [0402]
R777  10K  [0402]
R778  0  [0402]
R779  0  [0402]
R780  2.49K  [0402]
R781  1.78K  [0402]
R787  32.4K  [0402]
U86  IR3473  [qfn_supirbuck_4x5]
U87  IR3475  [qfn_supirbuck_4x5]
U88  IR3473  [qfn_supirbuck_4x5]
U89  IR3473  [qfn_supirbuck_4x5]
U90  IR3475  [qfn_supirbuck_4x5]
U91  IR3473  [qfn_supirbuck_4x5]

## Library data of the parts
C658 C669 C675 C685 = CAP: VOLTAGE: 200V
C659-C662 C664 C666-C668 C674 C690 C694 = CAP: VOLTAGE: 100V
C670-C672 C676 C698 C703 C705 C711 C722 C731 C736 C750 C752 C760 C781-C784 C787-C795 C932 C934 C936 C937 C939 C944 C946 C958-C960 C962 C968 C970 C982 C983 C985 C986 C992 C994 C1040 C1049 C1063 C1064 C1066-C1070 C1095-C1100 = CAP: VOLTAGE: 6.3V
C673 = CAP: BOM_IGNORE: DNP; VOLTAGE: 16V
C677-C681 C699-C701 C704 C706-C710 C712-C716 C720 C723 C729 C732 C735 C742-C749 C756 C762 C763 C765 C769 C779 C785 C796-C798 C924-C931 C933 C935 C940 C941 C947-C955 C961 C963-C965 C972-C976 C978-C980 C984 C987-C989 C997 C1044-C1048 C1050-C1058 C1101-C1105 C1112 C1113 = CAP: VOLTAGE: 16V
D22 = DIODE_SCHOTTKY: MPN: RB521S30T1G; TYPE: DIODE; Vendor: ON Semi
D40-D42 = LED: MPN: L-96A8YVP/1GD/TG-0L; Vendor: Kingbrignt
F5-F8 = PTC: MPN: MF-SM013/250V; Vendor: BOURNS
J23 = RJ11_6P_2: MPN: 8266-B01-R; TYPE: CON; Vendor: XMULTIPLE
J24 = RJ11_4P: MPN: 6053-6PXC11RXXX0210; TYPE: CON; Vendor: Shenzhen YTCO
J25 = TQ2-3V: TYPE: CON; Vendor: Panasonic
R441 R442 R445-R451 R453 R455 R464 R465 R468 R470-R472 R480-R490 R493-R509 R511 R516 R517 R520 R521 R525 R526 R530 R532 R533 R536 R537 R540-R561 R563 R564 R568-R570 R573 R574 R579 R588 R589 R593 R595 R720-R723 R726 R734 R737 R739 R742 R743 R752 R754 R756 R760 R761 R768 R770 R771 R773 R778 R779 R834 R836 R837 R839 R841-R844 R858 = RES: TOL: 5%
R444 R452 R459-R461 R466 R467 R469 R473 R474 R476 R478 R479 R562 R565 R566 R575 R576 R578 R580-R582 R586 R590 R591 R594 R596-R599 R728-R731 R733 R735 R736 R738 R744-R749 R751 R753 R755 R757 R762-R767 R769 R772 R774 R775 R780 R781 R787 = RES: TOL: 1%
R463 R475 R477 R519 R523 R524 R527 R528 R534 R535 R538 R835 R838 = RES: BOM_IGNORE: DNP; TOL: 1%
U62 U64 = TISP61089: MPN: TISP61089BDR-S; TYPE: IC; Vendor: Bourns
U63 = Le88266DLC: TYPE: IC; Vendor: Microsemi
C682 C684 C693 C696 C697 C733 C734 C738-C741 C764 C778 C942 C943 C966 C967 C990 C991 = CAP: VOLTAGE: 50V
C683 C718 C728 C766 C786 = CAP: BOM_IGNORE: DNP; VOLTAGE: 50V
C686 C688 C695 C702 C721 C730 C737 C751 C753-C755 C757 C758 C761 C770-C774 C945 C969 C971 C993 C995 C1000 C1001 C1041 C1075-C1078 = CAP: VOLTAGE: 25V
C687 C759 C775 = CAP_E: TYPE: CAP; VOLTAGE: 25V
C689 = CAP_E: TYPE: CAP; VOLTAGE: 100V
C691 C692 = CAP_E: TYPE: CAP; VOLTAGE: 50V
D25 D26 D28 = DIODE: Vendor: DIODES
D27 = DIODE_DUAL_A: TYPE: DIODE; Vendor: DIODES
FB46-FB48 FB50 FB52-FB55 = BEAD: Vendor: Murata
L6 = IND_IRON: MPN: SWRB0704C-221MT; TYPE: IND; Vendor: Sunlord
L7 = IND_IRON: MPN: SWRB0704C-101MT; TYPE: IND; Vendor: Sunlord
Q5 = TRANS_PNP: MPN: MMBT2907A-7-F; TYPE: TRAN; Vendor: DIODES
Q6 = NMOS: TYPE: MOS; Vendor: IR
Q7 = NMOS: TYPE: MOS; Vendor: FAIRCHILD
R491 = RES: TOL: 2%
T12 = XFMR_POTS_10PIN: TYPE: XFMR; Vendor: SUMIDA
J26 = CONN_2X5: MPN: TSW-105-07-F-D; TYPE: HDR; Vendor: Samtec
SW3 = SWITCH_DIP_8: MPN: DHNF-08F-V; TYPE: CON; Vendor: DIPTRONICS
U65 = EPM570F256: MPN: EPM570GF256C5N; TYPE: IC; Vendor: Altera
X2 = OSC: MPN: KK3270021; Vendor: PERICOM
R513 R518 R567 R592 R727 R732 R740 R741 R750 R758 R759 R776 R777 R829 = RES: BOM_IGNORE: DNP; TOL: 5%
U97 = IDT9FGV0641: MPN: 9FGV0641AKLF; TYPE: IC; Vendor: IDT
X3 X5 = OSC: MPN: 5x7mm,1.8V,+/-50ppm
Y4-Y6 = CRYSTAL_4PIN: MPN: 3.2x2.5mm,+/-20ppm; TYPE: XTAL
U67 U68 = ICS843002-01: MPN: 843002AG-01LF; TYPE: IC; Vendor: IDT
C767 C768 C776 C777 = CAP_E: MPN: 2R5TPE470M7; TYPE: CAP; VOLTAGE: 2.5V; Vendor: SANYO
J27 = JMP2: MPN: TSW-102-07-F-S; TYPE: HDR; Vendor: Samtec
J28 = CONN_1X3: MPN: TSW-103-07-F-S; TYPE: HDR; Vendor: Samtec
L8 L9 = IND_IRON: MPN: FP1007R3-R22-R; TYPE: IND; Vendor: Cooper Electronic
L23 = IND_IRON: MPN: IHLP2525CZER1R0M01; TYPE: IND; Vendor: Vishay
Q39 Q40 = NMOS: MPN: IRLML6346TRPBF; TYPE: MOS; Vendor: IR
R577 = RES_NTC: MPN: NCP18XH103F03RB; TYPE: RES; Vendor: Murata
U69 U71 = IR3550: MPN: IR3550MPBF; TYPE: IC; Vendor: IR
U70 = IR36021: MPN: IR36021MTRPBF; TYPE: IC; Vendor: IR
U72 = MIC39102-SOIC: TYPE: IC; Vendor: Micrel
U92 = ADG836: MPN: ADG836YRMZ; TYPE: IC; Vendor: ADI
C938 C956 C957 C977 C981 = CAP: BOM_IGNORE: DNP; VOLTAGE: 25V
J39 = CONN_1X2: MPN: TSW-102-07-F-S; TYPE: HDR; Vendor: Samtec
L17 L18 L22 = IND_IRON: MPN: IHLP2525CZER2R2M01; TYPE: IND; Vendor: Vishay
L19 L20 = IND_IRON: MPN: IHLP2525CZER3R3M01; TYPE: IND; Vendor: Vishay
L21 = IND_IRON: MPN: IHLP2525CZER4R7M01; TYPE: IND; Vendor: Vishay
U86 U88 U89 U91 = IR3475: MPN: IR3473MTR1PBF; TYPE: IC; Vendor: IR
U87 U90 = IR3475: MPN: IR3475MTR1PBF; TYPE: IC; Vendor: IR

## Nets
1V0: C933.1 C935.1 C937.1 C939.1 C1063.1 C1064.1 L17.2 R738.2 ; also on sheet 18 19 21
1V5: C959.1 C960.1 C961.1 C964.1 C1095.1 C1096.1 L19.2 R753.2 ; also on sheet 22
1V8_0641_VDD: C1049.1 C1050.1 C1051.1 FB55.2 R839.1 R841.1 U97.16(VDD1.8) U97.31(VDD1.8)
1V8_0641_VDDA: C736.1 C737.1 R841.2 U97.26(VDDA1.8)
1V8_0641_VDDIO: C1044.1 C1045.1 C1046.1 C1047.1 C1048.1 C1052.1 FB54.1 U97.5(VDDREF1.8) U97.12(VDDIO) U97.17(VDDIO) U97.27(VDDIO) U97.32(VDDIO) U97.39(VDDIO)
1V8_0641_VDDXTAL: C1040.1 C1041.1 R839.2 U97.4(VDDXTAL1.8)
1V8_SLP: C698.1 C699.1 C700.1 C735.1 C958.1 C962.1 C963.1 C965.1 C1097.1 C1098.1 C1101.1 FB54.2 FB55.1 L20.2 R533.1 R757.2 R829.1 R834.1 R843.1 R844.1 U65.H8(VCCINT) U65.H10(VCCINT) U65.J7(VCCINT) U65.J9(VCCINT) U97.11(VDDDIG1.8) ; also on sheet 12 31
1V35_SLP: C934.1 C936.1 C940.1 C941.1 C1069.1 C1070.1 L18.2 R736.2 ; also on sheet 3 12 31
2V5_SLP: C982.1 C983.1 C984.1 C988.1 C1099.1 C1100.1 L21.2 R774.2 ; also on sheet 7 8 12 15 31
3V3: C676.1 C677.1 C678.1 C679.1 C680.1 C681.1 C742.1 C743.1 C744.1 C745.1 D40.2 D41.2 D42.2 FB52.1 FB53.1 Q39.1(G) Q40.1(G) R442.2 R468.2 R540.1 R549.1 R550.1 R858.2 U63.7(AVDD) U63.25(DVDD) U63.37(DVDD) U63.54(AVDD) U63.57(AVDD) U67.10(VCC) U67.16(VCC) U68.10(VCC) U68.16(VCC) ; also on sheet 3 5 6 7 9 10 12 14 16 17 21 22 23 31 32
3V3_OSC_CPLD: C703.1 C704.1 FB47.2 R494.1 X2.4(VDD)
3V3_PGOOD: R771.2 U65.K1(IO_B1) U90.3(PGOOD)
3V3_SLP: C701.1 C702.1 C705.1 C706.1 C707.1 C708.1 C709.1 C710.1 C985.1 C986.1 C987.1 C989.1 C997.1 C1066.1 C1067.1 C1068.1 C1102.1 C1103.1 FB47.1 J26.4 L22.2 R497.1 R498.1 R559.2 R563.1 R564.1 R569.1 R570.1 R573.1 R574.1 R595.2 R771.1 R772.2 U65.C1(VCCIO1) U65.H6(VCCIO1) U65.J6(VCCIO1) U65.L8(VCCIO1) U65.L9(VCCIO1) U65.P1(VCCIO1) U65.T3(VCCIO1) U65.T14(VCCIO1) U92.8(VDD) ; also on sheet 7 11 12 13 15 31 32
3V3A_843002A: C750.1 C751.1 R549.2 U68.8(VCCA)
3V3A_843002B: C752.1 C753.1 R550.2 U67.8(VCCA)
3V3O_843002A: C746.1 C747.1 FB52.2 U68.2(VCCO) U68.20(VCCO)
3V3O_843002B: C748.1 C749.1 FB53.2 U67.2(VCCO) U67.20(VCCO)
5V0_SLP: C925.1 C926.1 C928.2 C929.2 C930.1 C931.1 C950.2 C951.2 C952.1 C953.1 C954.1 C955.1 C973.2 C974.2 C975.1 C976.1 C979.1 C980.1 C1053.2 C1054.2 C1055.2 C1056.2 C1057.2 C1058.2 C1112.1 C1113.1 R727.1 R728.1 R730.1 R732.1 R734.1 R737.1 R739.1 R746.1 R747.1 R750.1 R752.1 R754.1 R756.1 R764.1 R765.1 R768.1 R770.1 R773.1 U86.10(VCC) U86.13(VIN) U87.10(VCC) U87.13(VIN) U88.10(VCC) U88.13(VIN) U89.10(VCC) U89.13(VIN) U90.10(VCC) U90.13(VIN) U91.10(VCC) U91.13(VIN) ; also on sheet 11 32
7V0_DRV: C756.2 C769.2 C797.1 R558.1 R598.2 R727.2 U69.3(VCC) U69.27(~{BBRK}) U71.3(VCC) U71.27(~{BBRK}) U72.3(OUT)
12V: C686.1 FB46.1 ; also on sheet 10 22 31 32
12V_POTS: C687.1 C688.1 C695.1 D27.1 D27.2 FB46.2 Q5.2(E) R482.2 R483.2 R484.2 R485.2 T12.1
12V_SLP: C796.1 C1075.1 C1076.1 C1077.1 C1078.1 L23.2 R557.2 R597.1 U72.2(IN) ; also on sheet 31 32
12VF_SLP: C754.1 C755.1 C757.1 C758.1 C759.1 C771.1 C772.1 C773.1 C774.1 C775.1 C1000.1 C1001.1 L23.1 U69.18(VIN) U69.20(VIN) U69.21(VIN) U69.22(VIN) U69.23(VIN) U71.18(VIN) U71.20(VIN) U71.21(VIN) U71.22(VIN) U71.23(VIN)
GND: C658.2 C661.2 C662.1 C664.2 C667.1 C669.2 C670.1 C673.2 C674.2 C675.2 C676.2 C677.2 C678.2 C679.2 C680.2 C681.2 C684.2 C685.2 C686.2 C687.2 C688.2 C691.1 C692.1 C693.2 C694.2 C695.2 C697.2 C698.2 C699.2 C700.2 C701.2 C702.2 C703.2 C704.2 C705.2 C706.2 C707.2 C708.2 C709.2 C710.2 C711.2 C712.2 C713.2 C714.2 C715.2 C716.2 C718.2 C720.2 C721.2 C722.2 C723.2 C728.2 C729.2 C730.2 C731.2 C732.2 C733.2 C734.2 C735.2 C736.2 C737.2 C738.2 C739.2 C740.2 C741.2 C742.2 C743.2 C744.2 C745.2 C746.2 C747.2 C748.2 C749.2 C750.2 C751.2 C752.2 C753.2 C754.2 C755.2 C756.1 C757.2 C758.2 C759.2 C760.2 C761.2 C762.2 C767.2 C768.2 C769.1 C770.1 C771.2 C772.2 C773.2 C774.2 C775.2 C776.2 C777.2 C781.2 C782.2 C783.2 C784.2 C787.2 C788.2 C789.2 C790.2 C791.2 C792.2 C793.2 C794.2 C795.2 C796.2 C797.2 C798.1 C925.2 C926.2 C928.1 C929.1 C930.2 C931.2 C932.1 C933.2 C934.2 C936.2 C937.2 C938.1 C939.2 C940.2 C944.2 C945.2 C946.2 C947.2 C950.1 C951.1 C952.2 C953.2 C954.2 C955.2 C956.1 C957.1 C958.2 C959.2 C960.2 C961.2 C962.2 C963.2 C968.2 C969.2 C970.2 C971.2 C973.1 C974.1 C975.2 C976.2 C977.1 C979.2 C980.2 C981.1 C982.2 C983.2 C984.2 C985.2 C986.2 C987.2 C992.2 C993.2 C994.2 C995.2 C997.2 C1000.2 C1001.2 C1040.2 C1041.2 C1044.2 C1045.2 C1046.2 C1047.2 C1048.2 C1049.2 C1050.2 C1051.2 C1052.2 C1053.1 C1054.1 C1055.1 C1056.1 C1057.1 C1058.1 C1063.2 C1064.2 C1066.2 C1067.2 C1068.2 C1069.2 C1070.2 C1075.2 C1076.2 C1077.2 C1078.2 C1095.2 C1096.2 C1097.2 C1098.2 C1099.2 C1100.2 C1101.2 C1102.2 C1103.2 C1104.2 C1105.2 C1112.2 C1113.2 J26.2 J26.10 J27.2 J28.2 J39.2 Q7.2(S) R469.1 R480.1 R481.1 R487.1 R491.1 R493.1 R496.1 R499.2 R500.2 R501.2 R503.2 R505.2 R507.2 R509.2 R513.1 R518.1 R519.2 R523.2 R524.1 R527.2 R528.1 R534.2 R535.1 R538.1 R541.1 R542.1 R543.1 R544.1 R545.1 R546.1 R547.1 R548.1 R556.1 R560.1 R567.1 R568.1 R575.1 R581.2 R582.2 R588.2 R589.2 R592.1 R593.1 R594.1 R596.1 R599.1 R742.1 R743.1 R744.1 R745.1 R760.1 R761.1 R762.1 R763.1 R778.1 R779.1 R780.1 R781.1 R835.2 R838.2 R842.1 SW3.9 T12.7 U62.6 U62.7 U63.5(BGND1) U63.8(AGND) U63.19(SWISY) U63.23(DGND) U63.39(DGND) U63.43(SWISZ) U63.53(AGND) U63.56(AGND) U63.58(BGND2) U63.81(EPAD) U64.6 U64.7 U65.A1(GNDIO) U65.A16(GNDIO) U65.B2(GNDIO) U65.B15(GNDIO) U65.G7(GNDIO) U65.G8(GNDIO) U65.G9(GNDIO) U65.G10(GNDIO) U65.H7(GNDINT) U65.H9(GNDINT) U65.J8(GNDINT) U65.J10(GNDINT) U65.K7(GNDIO) U65.K8(GNDIO) U65.K9(GNDIO) U65.K10(GNDIO) U65.R2(GNDIO) U65.R15(GNDIO) U65.T1(GNDIO) U65.T16(GNDIO) U67.17(VEE) U68.17(VEE) U69.1(CSIN-) U69.2(CSIN+) U69.4(PGND) U69.16(PGND) U69.28(LGND) U69.29(REFIN) U69.31(TGND) U70.33(EPAD) U71.1(CSIN-) U71.2(CSIN+) U71.4(PGND) U71.16(PGND) U71.28(LGND) U71.29(REFIN) U71.31(TGND) U72.5(GND) U72.6(GND) U72.7(GND) U72.8(GND) U86.4(GND) U86.11(PGND) U86.17(GND) U87.4(GND) U87.11(PGND) U87.17(GND) U88.4(GND) U88.11(PGND) U88.17(GND) U89.4(GND) U89.11(PGND) U89.17(GND) U90.4(GND) U90.11(PGND) U90.17(GND) U91.4(GND) U91.11(PGND) U91.17(GND) U92.3(GND) U97.8(GNDDIG) U97.41(EPAD) X2.2(GND) X3.2(GND) X5.2(GND) Y4.2 Y4.4 Y5.2 Y5.4 Y6.2 Y6.4 ; also on sheet 3 4 5 6 7 8 9 10 11 12 13 14 15 16 17 18 19 20 21 22 23 31 32 33
VBATH: C658.1 C669.1 C675.1 D25.2 R460.1 U62.2 U63.1(VBM1) U63.3(VBH) U63.60(VBM2) U64.2 ; also on sheet 23
VBATL: C674.1 C693.1 C694.1 L7.2 R463.1 U63.69(VBL2) U63.79(VBL1) ; also on sheet 23
VDD_EN: U65.N5(IO_B1) ; also on sheet 31
VDD_EN_N: U65.N12(IO_B1) ; also on sheet 31
BOOT_FLASH_SEL: R502.2 SW3.4 U65.F15(IO_B2)
CFG_VBANK0: R504.2 SW3.5 U65.J16(IO_B2) ; also on sheet 5
CFG_VBANK1: R506.2 SW3.6 U65.H16(IO_B2) ; also on sheet 5
CFG_VBANK2: R508.2 SW3.7 U65.J15(IO_B2) ; also on sheet 5
CKE_ISO_EN: U65.L4(IO_B1) ; also on sheet 31
COP_HRESET_N: U65.G1(IO_B1) ; also on sheet 7
COP_SRESET_N: U65.H1(IO_B1) ; also on sheet 7
COP_TRST_N: U65.J1(IO_B1) ; also on sheet 7
CPLD_INT1_N: U65.E13(IO_B2) ; also on sheet 7
CPLD_INT2_N: U65.E14(IO_B2) ; also on sheet 7
CPLD_REFCLK: R495.2 U65.H5(GCLK0p)
CPLD_TCK: J26.1 R496.2 U65.P3(TCK)
CPLD_TDI: J26.9 R498.2 U65.L6(TDI)
CPLD_TDO: J26.3 U65.M5(TDO)
CPLD_TMS: J26.5 R497.2 U65.N4(TMS)
DDR_REFCLK: R517.2 R518.2 ; also on sheet 7
DDR_RST_N: U65.A2(IO_B2) ; also on sheet 3
DDRPWR_EN_N: U65.R4(IO_B1) ; also on sheet 31
DIFSYSCLK_OE_N: R844.2 U65.N15(IO_B2) U97.38(~{OE5})
EC1_RST_N: U65.H3(IO_B1) ; also on sheet 15
EC2_RST_N: U65.J2(IO_B1) ; also on sheet 16
EVDD_SEL: U65.F1(IO_B1) ; also on sheet 31
EVT_BRD_ISO: U65.K16(IO_B2) ; also on sheet 7
EVT_PWR_EN: U65.L15(IO_B2) ; also on sheet 7
EVT_PWR_OK: U65.L16(IO_B2) ; also on sheet 7
FAN_PWM: U65.E1(IO_B1) ; also on sheet 32
FXO_LED: R470.1 U65.F3(IO_B1)
FXO_RING: J24.2 J25.2
FXO_TIP: J24.3 J25.9
FXS1_LED: U65.E2(IO_B1) ; also on sheet 23
FXS2_LED: U65.D3(IO_B1) ; also on sheet 23
FXS3_LED: R471.1 U65.F2(IO_B1)
FXS4_LED: R472.1 U65.E3(IO_B1)
FXS_RING: J23.A3 J25.3
FXS_TIP: J23.A4 J25.8
GPIO_CKE_ISO: U65.P13(IO_B1) ; also on sheet 7
HRESET_N: U65.D14(IO_B2) ; also on sheet 7
I2C1_SCL: Q39.2(S) ; also on sheet 3 7 14
I2C1_SCL_SLP: J28.3 Q39.3(D) R570.2 U70.16(SM_CLK) U97.9(SCLK_3.3)
I2C1_SDA: Q40.2(S) ; also on sheet 3 7 14
I2C1_SDA_SLP: J28.1 Q40.3(D) R569.2 U70.15(SM_DIO) U97.10(SDATA_3.3)
IFC_A16: U65.D16(IO_B2) ; also on sheet 4 5
IFC_A17: U65.E15(IO_B2) ; also on sheet 4 5
IFC_A27: U65.C13(IO_B2) ; also on sheet 4 5
IFC_A28: U65.C12(IO_B2) ; also on sheet 4 5
IFC_A29: U65.C11(IO_B2) ; also on sheet 4 5
IFC_A30: U65.D12(IO_B2) ; also on sheet 4 5
IFC_A31: U65.A5(IO_B2) ; also on sheet 4
IFC_AD0: U65.A13(IO_B2) ; also on sheet 4 5
IFC_AD1: U65.B13(IO_B2) ; also on sheet 4 5
IFC_AD2: U65.B12(IO_B2) ; also on sheet 4 5
IFC_AD3: U65.A12(IO_B2) ; also on sheet 4 5
IFC_AD4: U65.A11(IO_B2) ; also on sheet 4 5
IFC_AD5: U65.B11(IO_B2) ; also on sheet 4 5
IFC_AD6: U65.B10(IO_B2) ; also on sheet 4 5
IFC_AD7: U65.A10(IO_B2) ; also on sheet 4 5
IFC_AD8: U65.A6(IO_B2) ; also on sheet 4 5
IFC_AD9: U65.B7(IO_B2) ; also on sheet 4 5
IFC_AD10: U65.A7(IO_B2) ; also on sheet 4 5
IFC_AD11: U65.B8(IO_B2) ; also on sheet 4 5
IFC_AD12: U65.A8(IO_B2) ; also on sheet 4 5
IFC_AD13: U65.C8(IO_B2) ; also on sheet 4 5
IFC_AD14: U65.A9(IO_B2) ; also on sheet 4 5
IFC_AD15: U65.B9(IO_B2) ; also on sheet 4 5
IFC_CLE: U65.D15(IO_B2) ; also on sheet 4 5
IFC_CLK: U65.J12(GCLK2p) ; also on sheet 4
IFC_CS0_N: U65.B6(IO_B2) ; also on sheet 4
IFC_CS1_N: U65.B5(IO_B2) ; also on sheet 4
IFC_CS2_N: U65.A4(IO_B2) ; also on sheet 4
IFC_LATCH_N: U65.B14(IO_B2) ; also on sheet 5
IFC_OE_N: SW3.2 U65.G15(IO_B2) ; also on sheet 4 5
IFC_RB0_N: U65.A15(IO_B2) ; also on sheet 4
IFC_RB1_N: U65.B16(IO_B2) ; also on sheet 4
IFC_WE_N: SW3.1 U65.H15(IO_B2) ; also on sheet 4 5
IFC_WP_N: SW3.3 U65.F16(IO_B2) ; also on sheet 4 5
IO_B1: U65.B1(IO_B2)
IO_B3: U65.B3(IO_B2)
IO_C4: U65.C4(IO_B2)
IO_C5: U65.C5(IO_B2)
IO_C6: U65.C6(IO_B2)
IO_C7: U65.C7(IO_B2)
IO_C9: U65.C9(IO_B2)
IO_C10: U65.C10(IO_B2)
IO_D4: U65.D4(IO_B2)
IO_D5: U65.D5(IO_B2)
IO_D11: U65.D11(IO_B2)
IO_F13: U65.F13(IO_B2)
IO_F14: U65.F14(IO_B2)
IO_G14: U65.G14(IO_B2)
IO_H14: U65.H14(IO_B2)
IO_J14: U65.J14(IO_B2)
IO_K14: U65.K14(IO_B2)
IO_L1: U65.L1(IO_B1)
IO_L13: U65.L13(IO_B2)
IO_L14: U65.L14(IO_B2)
IO_M13: U65.M13(IO_B2)
IO_M14: U65.M14(IO_B2)
IO_N1: U65.N1(IO_B1)
IO_N13: U65.N13(IO_B2)
IO_N14: U65.N14(IO_B2)
IO_P14: U65.P14(IO_B2)
IO_R1: U65.R1(IO_B1)
IO_R16: U65.R16(IO_B1)
IO_T6: U65.T6(IO_B1)
IO_T7: U65.T7(IO_B1)
IO_T8: U65.T8(IO_B1)
IO_T9: U65.T9(IO_B1)
IO_T10: U65.T10(IO_B1)
IO_T11: U65.T11(IO_B1)
IO_T12: U65.T12(IO_B1)
IO_T13: U65.T13(IO_B1)
IO_T15: U65.T15(IO_B1)
IOPWR_EN: C938.2 C956.2 R732.2 R750.2 U65.R8(IO_B1) U86.16(EN) U88.16(EN) ; also on sheet 31
IOPWR_EN_N: U65.P10(IO_B1) ; also on sheet 31
JTAG_TRST_N: U65.B4(IO_B2) ; also on sheet 7
LED_STATUS: U65.D2(IO_B1) ; also on sheet 32
LED_T1040_DET: U65.T4(IO_B1) ; also on sheet 13
LED_T2081_DET: U65.T5(IO_B1) ; also on sheet 13
LIFELINE: D22.2 J25.10 U63.24(I/O11)
MPEX1_REFCLK_N: R526.2 R528.2 ; also on sheet 22
MPEX1_REFCLK_P: R524.2 R525.2 ; also on sheet 22
MPEX1_RST_N: U65.T2(IO_B1) ; also on sheet 22
MPEX2_REFCLK_N: R532.2 R534.1 ; also on sheet 22
MPEX2_REFCLK_P: R527.1 R530.2 ; also on sheet 22
MPEX2_RST_N: U65.R3(IO_B1) ; also on sheet 22
NAND_CS_N: U65.G16(IO_B2) ; also on sheet 5
NAND_RB_N: U65.E4(IO_B1) ; also on sheet 5
NOR_CS_N: U65.D13(IO_B2) ; also on sheet 5
NOR_RST_N: U65.C14(IO_B2) ; also on sheet 5
OVDD: C729.1 C730.1 FB50.1 R502.1 R504.1 R506.1 R508.1 ; also on sheet 4 5 6 7 12 13
OVDD_OSC_DDR: C731.1 C732.1 FB50.2 R516.1 X5.4(VDD)
OVDD_OSC_SYS: C722.1 C723.1 FB48.2 X3.4(VDD)
OVDD_SLP: C711.1 C712.1 C713.1 C714.1 C715.1 C716.1 C720.1 C721.1 C1104.1 C1105.1 FB48.1 U65.A3(VCCIO2) U65.A14(VCCIO2) U65.C16(VCCIO2) U65.F8(VCCIO2) U65.F9(VCCIO2) U65.H11(VCCIO2) U65.J11(VCCIO2) U65.P16(VCCIO2) ; also on sheet 7 11 12 13
PEX2_SEL_N: U65.P6(IO_B1) ; also on sheet 9
PEX4_SEL_N: U65.R6(IO_B1) ; also on sheet 9
PEX_PRS_N: U65.P5(IO_B1) ; also on sheet 22
PEX_REFCLK_N: R521.2 R523.1 ; also on sheet 22
PEX_REFCLK_P: R519.1 R520.2 ; also on sheet 22
PEX_RST_N: U65.R5(IO_B1) ; also on sheet 22
PEXCLK_OE_N: R843.2 U65.N16(IO_B2) U97.13(~{OE0}) U97.24(~{OE2}) U97.30(~{OE3}) U97.35(~{OE4})
PORESET_N: U65.C15(IO_B2) ; also on sheet 7
POTS3_RING: F6.2 J25.4 R451.2
POTS3_TIP: F5.2 J25.7 R441.2
POTS4_RING: F8.2 J23.B3 R465.2
POTS4_TIP: F7.2 J23.B4 R464.2
POTS_RST_N: R455.1 ; also on sheet 23
POTS_SWCMP: C683.1 C684.1 R473.1 ; also on sheet 23
POTS_SWIS: C697.1 R488.2 ; also on sheet 23
POTS_SWOUT: R489.1 ; also on sheet 23
POTS_TDM_CLK: R445.1 ; also on sheet 7 23
POTS_TDM_FS: R446.1 ; also on sheet 7 23
POTS_TDM_RXD: R448.1 ; also on sheet 7 23
POTS_TDM_TXD: R447.1 ; also on sheet 7 23
POTSA_INT_N: U65.H2(IO_B1) ; also on sheet 23
POTSA_SWVSY: C682.2 C683.2 R474.1 R475.1 ; also on sheet 23
POTSA_SWVSZ: R478.1 ; also on sheet 23
POTSB_INT_N: R858.1 U63.31(~{INT}/S2) U65.K3(IO_B1)
POTSB_SPI_CS_N: R442.1 U63.36(~{CS}/PG) ; also on sheet 6
POTSB_SWVSY: R476.1 R477.1 U63.18(SWVSY)
POTSB_SWVSZ: R479.1 U63.44(SWVSZ)
PWR_GOOD: U65.C2(IO_B1) ; also on sheet 32
PWR_RST_N: U65.C3(IO_B1) ; also on sheet 32
QSG1_INT_N: U65.N2(IO_B1) ; also on sheet 18
QSG1_REFCLK_N: R548.2 U67.3(Q0) ; also on sheet 18
QSG1_REFCLK_P: R547.2 U67.4(~{Q0}) ; also on sheet 18
QSG1_RST_N: U65.M3(IO_B1) ; also on sheet 18
QSG2_INT_N: U65.P2(IO_B1) ; also on sheet 19
QSG2_REFCLK_N: R546.2 U67.19(Q1) ; also on sheet 19
QSG2_REFCLK_P: R545.2 U67.18(~{Q1}) ; also on sheet 19
QSG2_RST_N: U65.N3(IO_B1) ; also on sheet 19
RESET_REQ_N: U65.K15(IO_B2) ; also on sheet 7
SD_REFCLK1_N: R543.2 U68.4(~{Q0}) ; also on sheet 8
SD_REFCLK1_P: R544.2 U68.3(Q0) ; also on sheet 8
SD_REFCLK1_SEL: U65.M1(IO_B1) U68.9(F_SEL0)
SD_REFCLK2_N: R537.2 R538.2 ; also on sheet 8
SD_REFCLK2_P: R535.2 R536.2 ; also on sheet 8
SDHC_VS: U65.M16(IO_B2) ; also on sheet 7
SENSEGND: R554.2 ; also on sheet 12
SENSEGNDC: R555.1 ; also on sheet 12
SENSEVDD: R552.2 ; also on sheet 12
SENSEVDD_EN: U65.P7(IO_B1) U92.1(IN1) U92.5(IN2)
SENSEVDDC: R553.1 ; also on sheet 12
SFPP_DET_N: U65.L2(IO_B1) ; also on sheet 21
SFPP_RXLOS: U65.L3(IO_B1) ; also on sheet 21
SFPP_TXDIS: U65.K2(IO_B1) ; also on sheet 21
SFPP_TXFAIL: U65.J3(IO_B1) ; also on sheet 21
SG_INT_N: U65.M2(IO_B1) ; also on sheet 17
SG_RST_N: U65.R7(IO_B1) ; also on sheet 17
SPI_CLK: R450.1 ; also on sheet 6 10 23
SPI_CS3_SEL: U65.P9(IO_B1) ; also on sheet 10
SPI_MISO: R449.1 ; also on sheet 6 10 23
SPI_MOSI: R453.1 ; also on sheet 6 10 23
SYS_REFCLK: R511.2 R513.2 ; also on sheet 7
SYS_REFCLK_N: R837.2 R838.1 ; also on sheet 7
SYS_REFCLK_P: R835.1 R836.2 ; also on sheet 7
SYSCLK_OE: U65.M15(IO_B2) X3.1(OE)
T2081_DET_N: U65.P4(IO_B1) ; also on sheet 13
T2081_EN: U65.R9(IO_B1) ; also on sheet 9 31
TDMR1_INT_N: U65.R12(IO_B1) ; also on sheet 10
TDMR2_INT_N: U65.P11(IO_B1) ; also on sheet 10
TDMR_PRS_N: U65.P12(IO_B1) ; also on sheet 10
TDMR_RST_N: U65.R11(IO_B1) ; also on sheet 10
TDMR_SLP_N: U65.R13(IO_B1) ; also on sheet 10
TEST_SEL_N: SW3.8 U65.E16(IO_B2) ; also on sheet 7
THERM_ALERT_N: U65.M4(IO_B1) ; also on sheet 14
THERM_FAULT_N: U65.D1(IO_B1) ; also on sheet 14 32
VBH: C685.1 D25.1 L6.2 R480.2 R481.2
VBH1: D26.1 T12.10
VBH2: C689.2 D26.2 L6.1 R475.2 R477.2 R478.2 R479.2
VBL1: D28.1 T12.8
VBL2: C689.1 C691.2 C692.2 D28.2 L7.1 R474.2 R476.2
VCORE: C767.1 ; also on sheet 12 31
VCORE_EN: R564.2 U65.R14(IO_B1) U70.12(EN1)
VCORE_HOT_N: J27.1 R574.2 U65.P8(IO_B1) U70.11(~{VRHOT_ICRIT})
VCORE_IRTN1A: R566.1 U70.30(IRTN1A)
VCORE_IRTN1B: R591.1 U70.28(IRTN1B)
VCORE_ISEN1A: R565.1 U70.29(ISEN1A)
VCORE_ISEN1B: R590.1 U70.27(ISEN1B)
VCORE_PGOOD: R563.2 U65.R10(IO_B1) U70.7(PGOOD1)
VCORE_PWM1A: U69.26(PWM) U70.17(PWM1A)
VCORE_PWM1B: U70.18(PWM1B) U71.26(PWM)
VCORE_SLP: C765.2 C768.1 C776.1 C777.1 C781.1 C782.1 C783.1 C784.1 C785.2 C787.1 C788.1 C789.1 C790.1 C791.1 C792.1 C793.1 C794.1 L8.2 L9.2 R551.1 R566.2 R591.2 ; also on sheet 12 31
VCORE_SW1: C763.1 C766.1 L8.1 R562.1 U69.6(SW) U69.7(SW)
VCORE_SW2: C779.1 C786.1 L9.1 R586.1 U71.6(SW) U71.7(SW)
VCORE_VCC: C760.1 C762.1 R559.1 U70.22(VCC)
VCORE_VRTN1: C764.2 R555.2 R556.2 U70.3(VRTN1) U92.6(D2)
VCORE_VSEN1: C764.1 R551.2 R553.2 U70.2(VSEN1) U92.10(D1)
XG_LED0: U65.G3(IO_B1) ; also on sheet 21
XG_LED1: U65.G2(IO_B1) ; also on sheet 21
XG_REFCLK_N: R541.2 U68.18(~{Q1}) ; also on sheet 21
XG_REFCLK_P: R542.2 U68.19(Q1) ; also on sheet 21
XG_RST_N: U65.P15(IO_B2) ; also on sheet 21
N16851731: C696.2 R489.2 R490.1 R493.2
N16851789: C690.2 Q6.3(D) T12.4
N16851797: Q6.2(S) R488.1 R491.2
N16852263: C690.1 D27.3 R482.1 R483.1 R484.1
N16862179: Q7.1(G) R490.2
N16862407: Q5.3(C) Q7.3(D) R486.1
N16862426: C696.1 Q5.1(B) R485.1
N16862837: Q6.1(G) R486.2 R487.2
N17170143: C718.1 R511.1 X3.3(OUT)
N17232338: C728.1 R517.1 X5.3(OUT)
N17232433: R516.2 X5.1(OE)
N17257020: T12.2 T12.3
N17259940: C682.1 R473.2
N17285538: C733.1 U97.2(X1_25) Y4.1
N17285647: C734.1 U97.3(X2) Y4.3
N17448817: R448.2 U63.28(DXA/DU)
N17448821: R453.2 U63.34(DIN/S1)
N17448825: R455.2 U63.32(~{RST})
N17448833: R449.2 U63.35(DOUT)
N17448841: R466.2 U63.9(RTV1)
N17448842: R466.1 U63.6(RSN1)
N17448845: C672.2 U63.51(IHL2)
N17448846: C670.2 C671.1 C672.1 U63.17(VREF)
N17448848: C671.2 U63.10(IHL1)
N17448854: R467.1 U63.52(RTV2)
N17448855: R467.2 U63.55(RSN2)
N17448859: R469.2 U63.16(IREF)
N17448862: C673.1 U63.15(LFC1)
N17448864: C661.1 F5.1 R452.2 U62.1 U62.8 U63.77(TIPD1)
N17448865: C662.2 F6.1 R444.2 U62.4 U62.5 U63.71(RINGD1)
N17448866: R720.1 U63.13(TDC1)
N17448867: R721.1 U63.14(RDC1)
N17448868: C659.2 R452.1
N17448869: C659.1 U63.11(TAC1)
N17448871: C660.1 U63.12(RAC1)
N17448872: C660.2 R444.1
N17448897: C664.1 F7.1 R459.2 U63.67(TIPD2) U64.1 U64.8
N17448901: C667.2 F8.1 R461.2 U63.61(RINGD2) U64.4 U64.5
N17448912: C666.1 U63.50(TAC2)
N17448913: C668.1 U63.49(RAC2)
N17448914: R722.1 U63.47(RDC2)
N17448915: R723.1 U63.48(TDC2)
N17449042: R460.2 R463.2 U63.45(XB)
N17449050: R447.2 U63.29(DRA/DD)
N17449051: R446.2 U63.26(FS/FSC)
N17449052: C666.2 R459.1
N17449053: C668.2 R461.1
N17451420: D22.1 J25.1 R468.1
N17540598: R445.2 U63.30(PCLK/DCL)
N17540619: R450.2 U63.33(DCLK/S0)
N18382428: R499.1 SW3.16
N18382505: R500.1 SW3.15
N18382570: R501.1 SW3.14
N18382580: R503.1 SW3.13
N18382664: R507.1 SW3.11
N18382676: R509.1 SW3.10
N18635664: D40.1 R470.2
N18636077: D41.1 R471.2
N18636082: D42.1 R472.2
N18669250: C761.1 R557.1 R560.2 U70.9(VINSEN)
N18669461: R568.2 U70.8(EN2)
N18669908: R573.2 U70.14(SM_ALERT)
N18671161: C770.2 R575.2 U70.13(ADDR_PROT)
N18671661: C778.1 R576.2 U70.31(RCSP1)
N18671664: C778.2 R580.2 U70.32(RCSM1)
N18671728: R577.1 R578.1 R580.1
N18671731: R576.1 R577.2 R578.2
N18672102: R594.2 U70.4(RRES)
N18672710: C795.1 R595.1 U70.6(V18A)
N18673934: R581.1 U70.25(ISEN2)
N18674032: R582.1 U70.26(IRTN2)
N18675394: R561.1 U69.24(BOOST)
N18676216: C763.2 R561.2
N18677032: C765.1 R562.2 R565.2
N18677238: R558.2 U69.25(~{PHSFLT}) U71.25(~{PHSFLT})
N18679447: R579.1 U71.24(BOOST)
N18679579: C779.2 R579.2
N18679604: C785.1 R586.2 R590.2
N18708218: R588.1 U70.21(VSEN2)
N18708230: R589.1 U70.20(VRTN2)
N18709569: R593.2 U70.5(TSEN)
N18711479: R598.1 R599.2 U72.4(ADJ)
N19126530: R505.1 SW3.12
N19163046: R495.1 X2.3(OUT)
N19163064: R494.2 X2.1(OE)
N19211889: C766.2 R567.2
N19212054: C786.2 R592.2
N19214297: C798.2 R596.2 R597.2 U72.1(EN)
N19535162: R441.1 R720.2
N19535165: R451.1 R721.2
N19535242: R465.1 R723.2
N19535245: R464.1 R722.2
N19644915: C927.2 L18.1 R731.2 R735.1 U87.12(PHASE)
N19644936: C941.2 C943.2 R735.2
N19644956: C943.1 R736.1 R745.2 R787.2 U87.5(FB)
N19644972: R739.2 U87.3(PGOOD)
N19644986: C932.2 R734.2 U87.16(EN)
N19645019: C946.1 R741.1 U87.8(3VCBP)
N19645035: R741.2 R743.2 U87.1(FCCM)
N19645080: C947.1 U87.6(SS)
N19645160: R728.2 U87.15(FF)
N19645192: C927.1 U87.14(BOOT)
N19645200: R731.1 U87.2(ISET)
N19646811: C949.2 L20.1 R749.2 R755.1 U89.12(PHASE)
N19646830: C965.2 C967.2 R755.2
N19646848: C967.1 R757.1 R763.2 U89.5(FB)
N19646866: R749.1 U89.2(ISET)
N19646870: R756.2 U89.3(PGOOD)
N19646891: C957.2 R754.2 U89.16(EN)
N19646930: C970.1 R759.1 U89.8(3VCBP)
N19646940: R759.2 R761.2 U89.1(FCCM)
N19646995: C971.1 U89.6(SS)
N19647070: R747.2 U89.15(FF)
N19647102: C949.1 U89.14(BOOT)
N19648273: C978.2 L22.1 R767.2 R775.1 U90.12(PHASE)
N19648275: C989.2 C991.2 R775.2
N19648310: C991.1 R772.1 R781.2 U90.5(FB)
N19648328: R767.1 U90.2(ISET)
N19648366: C981.2 R770.2 U90.16(EN)
N19648414: C994.1 R777.1 U90.8(3VCBP)
N19648420: R777.2 R779.2 U90.1(FCCM)
N19648465: C995.1 U90.6(SS)
N19648544: R765.2 U90.15(FF)
N19648572: C978.1 U90.14(BOOT)
N19650144: C972.2 L21.1 R766.2 R769.1 U91.12(PHASE)
N19650163: C988.2 C990.2 R769.2
N19650181: C990.1 R774.1 R780.2 U91.5(FB)
N19650199: R766.1 U91.2(ISET)
N19650212: R773.2 U91.3(PGOOD)
N19650233: C977.2 R768.2 U91.16(EN)
N19650272: C992.1 R776.1 U91.8(3VCBP)
N19650282: R776.2 R778.2 U91.1(FCCM)
N19650331: C993.1 U91.6(SS)
N19650402: R764.2 U91.15(FF)
N19650430: C972.1 U91.14(BOOT)
N19651609: C948.2 L19.1 R748.2 R751.1 U88.12(PHASE)
N19651628: C964.2 C966.2 R751.2
N19651646: C966.1 R753.1 R762.2 U88.5(FB)
N19651664: R748.1 U88.2(ISET)
N19651683: R752.2 U88.3(PGOOD)
N19651731: C968.1 R758.1 U88.8(3VCBP)
N19651747: R758.2 R760.2 U88.1(FCCM)
N19651788: C969.1 U88.6(SS)
N19651863: R746.2 U88.15(FF)
N19651895: C948.1 U88.14(BOOT)
N19653096: C924.2 L17.1 R729.2 R733.1 U86.12(PHASE)
N19653107: C935.2 C942.2 R733.2
N19653133: C942.1 R738.1 R744.2 U86.5(FB)
N19653151: R729.1 U86.2(ISET)
N19653170: R737.2 U86.3(PGOOD)
N19653218: C944.1 R740.1 U86.8(3VCBP)
N19653234: R740.2 R742.2 U86.1(FCCM)
N19653275: C945.1 U86.6(SS)
N19653350: R730.2 U86.15(FF)
N19653382: C924.1 U86.14(BOOT)
N19673378: R726.1 U70.24(RCSP2)
N19673381: R726.2 U70.23(RCSM2)
N19825990: J39.1 R787.1
N20075552: R552.1 U92.2(S1A)
N20075564: R554.1 U92.4(S2A)
N20977401: C739.1 U68.13(XTAL_IN) Y5.1
N20977407: C738.1 U68.12(XTAL_OUT) Y5.3
N20978279: C740.1 U67.13(XTAL_IN) Y6.1
N20978303: C741.1 U67.12(XTAL_OUT) Y6.3
N20978493: R540.2 U67.9(F_SEL0)
N20980151: R829.2 R842.2 U97.1(SS_EN_TRI)
N20982998: R834.2 U97.6(SADR/REF1.8)
N21105612: R525.1 U97.22(DIF2)
N21105614: R526.1 U97.23(~{DIF2})
N21105620: R530.1 U97.28(DIF3)
N21105622: R532.1 U97.29(~{DIF3})
N21105628: R536.1 U97.33(DIF4)
N21105630: R537.1 U97.34(~{DIF4})
N21105856: R837.1 U97.37(~{DIF5})
N21105862: R836.1 U97.36(DIF5)
N22254280: R520.1 U97.14(DIF0)
N22254282: R521.1 U97.15(~{DIF0})
N22255501: R533.2 U97.21(~{OE1})

Not connected (* = marked no-connect by the designer): J23 A1* A2* A5* A6* B1* B2* B5* B6*; J24 1* 4*; J25 5* 6*; J26 6* 7* 8*; T12 5* 6* 9*; U62 3*; U63 2(RSVD1)* 4(RSVD2)* 20(SWCMPY)* 21(SWOUTY)* 22(I/O21)* 27(~{TSCA})* 38(I/O12)* 40(I/O22)* 41(SWOUTZ)* 42(SWCMPZ)* 46(LFC2)* 59(RSVD3)* 62(RSVD4)* 63(RSVD5)* 64(RSVD6)* 65(RSVD7)* 66(RSVD8)* 68(RSVD9)* 70(RSVD10)* 72(RSVD11)* 73(RSVD12)* 74(RSVD13)* 75(RSVD14)* 76(RSVD15)* 78(RSVD16)* 80(RSVD17)*; U64 3*; U65 D6(NC)* D7(NC)* D8(NC)* D9(NC)* D10(NC)* E5(NC)* E6(NC)* E7(NC)* E8(NC)* E9(NC)* E10(NC)* E11(NC)* E12(NC)* F4(NC)* F5(NC)* F6(NC)* F7(NC)* F10(NC)* F11(NC)* F12(NC)* G4(NC)* G5(NC)* G6(NC)* G11(NC)* G12(NC)* G13(NC)* H4(NC)* H12(GCLK3p)* H13(NC)* J4(NC)* J5(GCLK1p)* J13(NC)* K4(NC)* K5(NC)* K6(NC)* K11(NC)* K12(NC)* K13(NC)* L5(NC)* L7(NC)* L10(NC)* L11(NC)* L12(NC)* M6(NC)* M7(NC)* M8(DEV_OE)* M9(DEV_CLRn)* M10(NC)* M11(NC)* M12(NC)* N6(NC)* N7(NC)* N8(NC)* N9(NC)* N10(NC)* N11(NC)*; U67 1(NC1)* 5(MR)* 6(~{PLL_SEL})* 7(NC2)* 11(F_SEL1)* 14(TEST_CLK)* 15(~{XTAL_SEL})*; U68 1(NC1)* 5(MR)* 6(~{PLL_SEL})* 7(NC2)* 11(F_SEL1)* 14(TEST_CLK)* 15(~{XTAL_SEL})*; U69 5(GATEL1)* 30(IOUT)* 32(GATEL2)*; U70 1(PGOOD2)* 10(NC)* 19(PWM2)*; U71 5(GATEL1)* 30(IOUT)* 32(GATEL2)*; U86 7(NC1)* 9(NC2)*; U87 7(NC1)* 9(NC2)*; U88 7(NC1)* 9(NC2)*; U89 7(NC1)* 9(NC2)*; U90 7(NC1)* 9(NC2)*; U91 7(NC1)* 9(NC2)*; U92 7(S2B)* 9(S1B)*; U97 7(NC1)* 18(DIF1)* 19(~{DIF1})* 20(NC2)* 25(NC3)* 40(~{CKPWRGD_PD})*

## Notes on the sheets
sheet 24
- POTS 3&4 INTERFACE
- T1040 ONLY!
sheet 25
- POTS VBAT POWER SUPPLY
- T1040 ONLY!
sheet 26
- CPLD
- 3.3V BANK1 IO
- 1.8V/3.3V BANK2 IO
- cfg
- cfg
- cfg
- cfg
- cfg
- cfg
- cfg
- cfg
- OD OUTPUT
- OD OUTPUT
- cfg
- cfg
- cfg
- cfg
- cfg
- cfg
- OD OUTPUT
- OD OUTPUT
- OD OUTPUT(INTERPOSER)
- OD OUTPUT(INTERPOSER)
- cfg
- CPLD JTAG CONNECTOR
- cfg_eng_use0
- cfg_eng_use1
- cfg_eng_use2
sheet 27
- SYSTEM CLOCK GENERATORs
- I2C ADDR = 0x6A
- Integrated output terminations providing Zo=100
- DEFAULT NO SPREAD
sheet 28
- SYSTEM CLOCK GENERATORs (cont.)
- LOW: 156.25MHz FOR T2081
- HIGH: 125MHz FOR T1040
- T1040 ONLY!
- 125MHz
sheet 29
- T1040 CORE POWER CONVERTOR
- To assure sensing is in place with no processor
- Important! Normal operation, switch is closed,
  but when going to sleep (and after cores are disabled),
  switch must be opened BEFORE power FET for VDD is turned off.
  Then when coming out of sleep, first turn on power FET for VDD,
  then close sense switch, then enable cores.
  This assures that there is no sensing of unstable or zero voltages.
- When T2081, sleep mode is not used,
  may simply keep sense switch closed
  (SENSVDDC/SENSEGNDC pins are open when T2081).
- For the first programming
  of the internal flash:
  VR_HOT, EN
  need to be connected to GND. via
  short Jumper and CPLD will drive
  both enables low.
  (I2C address in this mode 0Ah)
- PROGRAMING CONNECTOR
- LABEL = PROG_VCORE
- FP1007R3-R22-R
- Irms = 61A
- DCR = 0.29mohm +/-5%
- Isat@125 = 43A
- 4 x POSCAP
- 2R5TPE470M7
- ESR = 7mohm
- Snubber Circuit
- STUFF IR3553
- PMBus Address offset to "+2"
- PLACE
  THERMISTOR
  NEAR L8&L9
- FP1007R3-R22-R
- COPPER PLANE
- Irms = 61A
- Isat@125 = 43A
- DCR = 0.29mohm +/-5%
- 12 x 22uF,0805,6.3V
- Snubber Circuit
- STUFF IR3553
- If 5.0V for IR3553 is OK, DNP the 7.0V LDO
- PowIRstage MOSFET Driver power supply
- Make sure 7.0V supply is applied
  after 3.3V is ready
- 7.0V supply is ramped down
  before 3.3V supply
sheet 30
- SYSTEM POWER CONVERTORs
- 2.2uH(IHLP2525CZER2R2M01): Irms = 8A, Isat = 14A, DCR = 18mohm
- 3.3uH(IHLP2525CZER3R3M01): Irms = 6A, Isat = 13.5A, DCR = 28mohm
- COPPER ISLAND
- 4.7uH(IHLP2525CZER4R7M01): Irms = 5.5A, Isat = 10A, DCR = 37mohm
- COPPER ISLAND
- MAX 10A
- Rff(kohm) = Vout/(1Vx20pFxFsw)
- SWITCHABLE
- COPPER PLANE
- Rff(kohm) = Vout/(1Vx20pFxFsw)
- ALWAYS ON
- COPPER PLANE
- Fsw = 400KHz
- Rset = 24(mohm)xIoc/19(uA)
- Fsw = 400KHz
- Rset = 13(mohm)xIoc/19(uA)
- Vout = 0.5x(Rtop/Rbot+1)
- Vout = 0.5x(Rtop/Rbot+1)
- Enable DCM Mode
- Enable DCM Mode
- LABEL = DDR3 VOLTAGE
- Css(nF) = 22xTss(mS)
- 1V35 POWER ON LAST
- Css(nF) = 22xTss(mS)
- INSTALL JUMPER FOR
  DDR3 1.5V
- FOR INTERPOSER MUST INSTALL JUMPER
- COPPER ISLAND
- COPPER ISLAND
- Rff(kohm) = Vout/(1Vx20pFxFsw)
- SWITCHABLE
- COPPER PLANE
- Rff(kohm) = Vout/(1Vx20pFxFsw)
- ALWAYS ON
- COPPER PLANE
- Fsw = 400KHz
- Rset = 24(mohm)xIoc/19(uA)
- Fsw = 400KHz
- Rset = 24(mohm)xIoc/19(uA)
- Vout = 0.5x(Rtop/Rbot+1)
- Vout = 0.5x(Rtop/Rbot+1)
- Enable DCM Mode
- Enable DCM Mode
- Css(nF) = 22xTss(mS)
- Css(nF) = 22xTss(mS)
- COPPER ISLAND
- COPPER ISLAND
- MAX 10A
- Rff(kohm) = Vout/(1Vx20pFxFsw)
- ALWAYS ON
- COPPER PLANE
- Rff(kohm) = Vout/(1Vx20pFxFsw)
- ALWAYS ON
- COPPER PLANE
- Fsw = 400KHz
- Rset = 24(mohm)xIoc/19(uA)
- Fsw = 400KHz
- Rset = 13(mohm)xIoc/19(uA)
- Vout = 0.5x(Rtop/Rbot+1)
- Vout = 0.5x(Rtop/Rbot+1)
- Enable DCM Mode
- Enable DCM Mode
- Css(nF) = 22xTss(mS)
- Css(nF) = 22xTss(mS)
- Caution: separate analog and power ground and make connection at GND plane
